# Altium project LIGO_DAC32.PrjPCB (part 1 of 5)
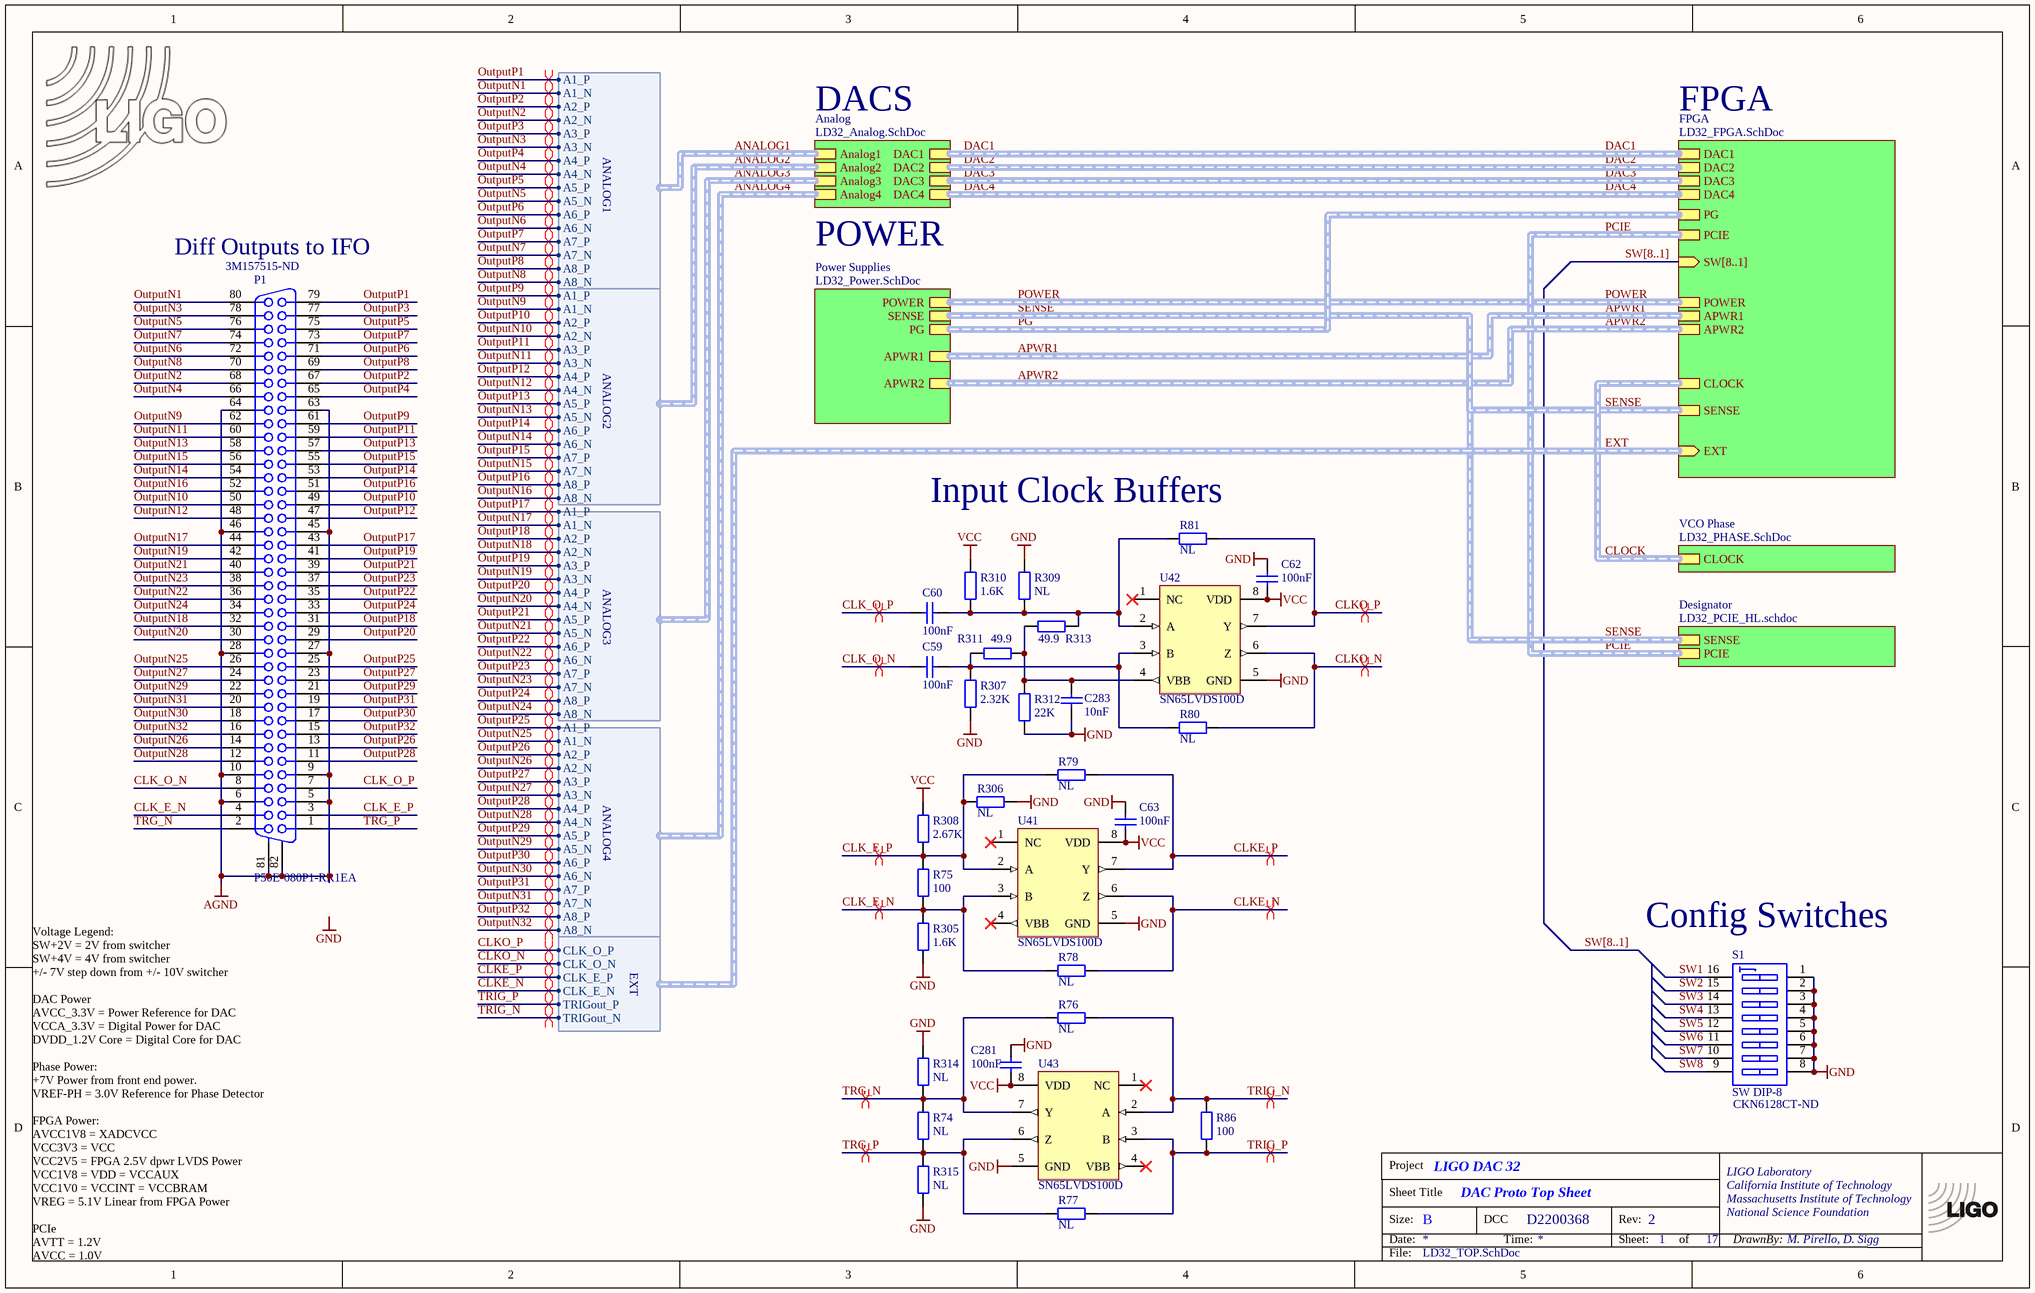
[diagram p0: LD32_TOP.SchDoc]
DCC: D2200368; DCCRevision: 2; ENG: M. Pirello, D. Sigg; Project: LIGO DAC 32; REV: 2; SHEETSIZE: B
17 sheets, 1238 parts. Net scope: hierarchical (ports join the sheet entries above them; power ports are global).
Board file: LD32.PcbDoc
Sheets:
  LD32_TOP.SchDoc
    Analog = LD32_Analog.SchDoc
      I1 = LD32_Outputs.SchDoc
         = LD32_DAC.SchDoc
           = LD32_FrontEnd.SchDoc
           = LD32_FrontEnd.SchDoc
           = LD32_FrontEnd.SchDoc
           = LD32_FrontEnd.SchDoc
      I2 = LD32_Outputs.SchDoc
         = LD32_DAC.SchDoc
           = LD32_FrontEnd.SchDoc
           = LD32_FrontEnd.SchDoc
           = LD32_FrontEnd.SchDoc
           = LD32_FrontEnd.SchDoc
      I3 = LD32_Outputs.SchDoc
         = LD32_DAC.SchDoc
           = LD32_FrontEnd.SchDoc
           = LD32_FrontEnd.SchDoc
           = LD32_FrontEnd.SchDoc
           = LD32_FrontEnd.SchDoc
      I4 = LD32_Outputs.SchDoc
         = LD32_DAC.SchDoc
           = LD32_FrontEnd.SchDoc
           = LD32_FrontEnd.SchDoc
           = LD32_FrontEnd.SchDoc
           = LD32_FrontEnd.SchDoc
    FPGA = LD32_FPGA.SchDoc
      FPGA INTERFACE = FPGA_ARTIX7.SchDoc
      ADC = LD32_XADC.SchDoc
      PRG = LD32_FLASH.SchDoc
    VCO Phase = LD32_PHASE.SchDoc
    Designator = LD32_PCIE_HL.SchDoc
      ChassisTimingInterfacePCIE = LD32_PCIE.SchDoc
    Power Supplies = LD32_Power.SchDoc
      Diff Power = LD32_Bipolar1.SchDoc
      Linear Supplies = LD32_Linear1.SchDoc
      Pos Power = LD32_Bipolar2.SchDoc
      PowerFPGA = LD32_PowerFPGA.SchDoc

## Sheet LD32_TOP.SchDoc: DAC Proto Top Sheet
size B; SheetNumber: 1; SheetTotal: 17; PageSetup: Record=PageOptions¦CenterHorizontal=True¦CenterVertical=True¦PrintScale=1.12¦XCorrection=1.00¦YCorrection=1.00¦PrintKind=0¦BorderSize=5000000¦LeftOffset=0¦BottomOffset=0¦Orientation=2¦PaperLength=1000¦PaperWidth=1000¦Scale=100¦PaperSource=7¦PrintQuality=-4¦MediaType=1¦DitherType=10¦PaperKind=Letter¦PrintScaleMode=1

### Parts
(Parts that share a designator on the sheet are numbered #1, #2 ... from top to bottom, then left to right.)
*?#1  TitleBlock  (value not drawn)  (graphical)
C59  100nF  [CC1005-0402]
C60  100nF  [CC1005-0402]
C62  100nF  [CC1005-0402]
C63  100nF  [CC1005-0402]
C281  100nF  [CC1005-0402]
C283  10nF  [CC1005-0402]
LOGO1  LIGO logo  [LIGO-LOGO-SM]  (value not drawn)  (no BOM)
P1  P50E-080P1-RR1EA  Supplier Part Number 1: 3M157515-ND  [P50E-080-SR1]
R74  NL  [CR1005-0402]
R75  100  [CR1005-0402]
R76  NL  [CR1005-0402]
R77  NL  [CR1005-0402]
R78  NL  [CR1005-0402]
R79  NL  [CR1005-0402]
R80  NL  [CR1005-0402]
R81  NL  [CR1005-0402]
R86  100  [CR1005-0402]
R305  1.6K  [CR1005-0402]
R306  NL  [CR1005-0402]
R307  2.32K  [CR1005-0402]
R308  2.67K  [CR1005-0402]
R309  NL  [CR1005-0402]
R310  1.6K  [CR1005-0402]
R311  49.9  [CR1005-0402]
R312  22K  [CR1005-0402]
R313  49.9  [CR1005-0402]
R314  NL  [CR1005-0402]
R315  NL  [CR1005-0402]
S1  SW DIP-8  Supplier Part Number 1: CKN6128CT-ND  [DIP_SW_8WAY_SMD_SIDE]
U41  SN65LVDS100D  [MSOP8]
U42  SN65LVDS100D  [MSOP8]
U43  SN65LVDS100D  [MSOP8]

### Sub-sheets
Analog = LD32_Analog.SchDoc: Analog1 (harness ANALOG1), Analog2 (harness ANALOG2), Analog3 (harness ANALOG3), Analog4 (harness ANALOG4), DAC1 (harness DAC1), DAC2 (harness DAC2), DAC3 (harness DAC3), DAC4 (harness DAC4)
Designator = LD32_PCIE_HL.schdoc: PCIE (harness PCIE), SENSE (harness SENSE)
FPGA = LD32_FPGA.SchDoc: DAC4 (harness S1_16), DAC3 (harness S17_32), DAC2 (harness S33_48), DAC1 (harness S49_64), CLOCK (harness CLOCK), PCIE (harness PCIE), POWER (harness POWER), APWR1 (harness CONFIG), APWR2 (harness CONFIG), SW[8..1] (in), PG (harness APWR2), SENSE (harness SENSE), EXT (in, harness EXT)
Power Supplies = LD32_Power.SchDoc: PG (harness APWR2), SENSE (harness SENSE), APWR1 (harness APWR2), APWR2 (harness APWR2), POWER (harness POWER)
VCO Phase = LD32_PHASE.SchDoc: CLOCK (harness CLOCK)

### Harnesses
EXT: CLK_O_N, CLK_E_P, CLK_E_N, CLK_O_P, TRIGout_P, TRIGout_N
ANALOG1: A1_P, A2_P, A2_N, A1_N, A3_P, A4_P, A4_N, A3_N, A5_P, A6_P, A6_N, A5_N, A7_P, A8_P, A8_N, A7_N
ANALOG2: A1_P, A2_P, A2_N, A1_N, A3_P, A4_P, A4_N, A3_N, A5_P, A6_P, A6_N, A5_N, A7_P, A8_P, A8_N, A7_N
ANALOG3: A1_P, A2_P, A2_N, A1_N, A3_P, A4_P, A4_N, A3_N, A5_P, A6_P, A6_N, A5_N, A7_P, A8_P, A8_N, A7_N
ANALOG4: A1_P, A2_P, A2_N, A1_N, A3_P, A4_P, A4_N, A3_N, A5_P, A6_P, A6_N, A5_N, A7_P, A8_P, A8_N, A7_N

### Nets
AGND: P1.5 P1.6 P1.9 P1.10 P1.27 P1.28 P1.45 P1.46 P1.63 P1.64 P1.81(MH1) P1.82(MH2)
GND: C62.1 C63.1 C281.1 C283.1 R305.2 R306.2 R307.2 R309.1 R312.2 R314.1 R315.2 S1.1(A1) S1.2(A2) S1.3(A3) S1.4(A4) S1.5(A5) S1.6(A6) S1.7(A7) S1.8(A8) U41.5(GND) U42.5(GND) U43.5(GND)
VCC: C62.2 C63.2 C281.2 R308.1 R310.1 U41.8(VDD) U42.8(VDD) U43.8(VDD)
CLK_E_N: P1.4 R75.2 R78.1 R305.1 U41.3(B)
CLK_E_P: P1.3 R75.1 R79.1 R306.1 R308.2 U41.2(A)
CLK_O_N: C59.1 P1.8
CLK_O_P: C60.1 P1.7
CLKE_N: R78.2 U41.6(Z) ; sheet FPGA/EXT.CLK_E_N
CLKE_P: R79.2 U41.7(Y) ; sheet FPGA/EXT.CLK_E_P
CLKO_N: R80.2 U42.6(Z) ; sheet FPGA/EXT.CLK_O_N
CLKO_P: R81.2 U42.7(Y) ; sheet FPGA/EXT.CLK_O_P
OutputN1: P1.80 ; sheet Analog/Analog1.A1_N  [project net ANALOG1.A1_N]
OutputN2: P1.68 ; sheet Analog/Analog1.A2_N  [project net ANALOG1.A2_N]
OutputN3: P1.78 ; sheet Analog/Analog1.A3_N  [project net ANALOG1.A3_N]
OutputN4: P1.66 ; sheet Analog/Analog1.A4_N  [project net ANALOG1.A4_N]
OutputN5: P1.76 ; sheet Analog/Analog1.A5_N  [project net ANALOG1.A5_N]
OutputN6: P1.72 ; sheet Analog/Analog1.A6_N  [project net ANALOG1.A6_N]
OutputN7: P1.74 ; sheet Analog/Analog1.A7_N  [project net ANALOG1.A7_N]
OutputN8: P1.70 ; sheet Analog/Analog1.A8_N  [project net ANALOG1.A8_N]
OutputN9: P1.62 ; sheet Analog/Analog2.A1_N  [project net ANALOG2.A1_N]
OutputN10: P1.50 ; sheet Analog/Analog2.A2_N  [project net ANALOG2.A2_N]
OutputN11: P1.60 ; sheet Analog/Analog2.A3_N  [project net ANALOG2.A3_N]
OutputN12: P1.48 ; sheet Analog/Analog2.A4_N  [project net ANALOG2.A4_N]
OutputN13: P1.58 ; sheet Analog/Analog2.A5_N  [project net ANALOG2.A5_N]
OutputN14: P1.54 ; sheet Analog/Analog2.A6_N  [project net ANALOG2.A6_N]
OutputN15: P1.56 ; sheet Analog/Analog2.A7_N  [project net ANALOG2.A7_N]
OutputN16: P1.52 ; sheet Analog/Analog2.A8_N  [project net ANALOG2.A8_N]
OutputN17: P1.44 ; sheet Analog/Analog3.A1_N  [project net ANALOG3.A1_N]
OutputN18: P1.32 ; sheet Analog/Analog3.A2_N  [project net ANALOG3.A2_N]
OutputN19: P1.42 ; sheet Analog/Analog3.A3_N  [project net ANALOG3.A3_N]
OutputN20: P1.30 ; sheet Analog/Analog3.A4_N  [project net ANALOG3.A4_N]
OutputN21: P1.40 ; sheet Analog/Analog3.A5_N  [project net ANALOG3.A5_N]
OutputN22: P1.36 ; sheet Analog/Analog3.A6_N  [project net ANALOG3.A6_N]
OutputN23: P1.38 ; sheet Analog/Analog3.A7_N  [project net ANALOG3.A7_N]
OutputN24: P1.34 ; sheet Analog/Analog3.A8_N  [project net ANALOG3.A8_N]
OutputN25: P1.26 ; sheet Analog/Analog4.A1_N  [project net ANALOG4.A1_N]
OutputN26: P1.14 ; sheet Analog/Analog4.A2_N  [project net ANALOG4.A2_N]
OutputN27: P1.24 ; sheet Analog/Analog4.A3_N  [project net ANALOG4.A3_N]
OutputN28: P1.12 ; sheet Analog/Analog4.A4_N  [project net ANALOG4.A4_N]
OutputN29: P1.22 ; sheet Analog/Analog4.A5_N  [project net ANALOG4.A5_N]
OutputN30: P1.18 ; sheet Analog/Analog4.A6_N  [project net ANALOG4.A6_N]
OutputN31: P1.20 ; sheet Analog/Analog4.A7_N  [project net ANALOG4.A7_N]
OutputN32: P1.16 ; sheet Analog/Analog4.A8_N  [project net ANALOG4.A8_N]
OutputP1: P1.79 ; sheet Analog/Analog1.A1_P  [project net ANALOG1.A1_P]
OutputP2: P1.67 ; sheet Analog/Analog1.A2_P  [project net ANALOG1.A2_P]
OutputP3: P1.77 ; sheet Analog/Analog1.A3_P  [project net ANALOG1.A3_P]
OutputP4: P1.65 ; sheet Analog/Analog1.A4_P  [project net ANALOG1.A4_P]
OutputP5: P1.75 ; sheet Analog/Analog1.A5_P  [project net ANALOG1.A5_P]
OutputP6: P1.71 ; sheet Analog/Analog1.A6_P  [project net ANALOG1.A6_P]
OutputP7: P1.73 ; sheet Analog/Analog1.A7_P  [project net ANALOG1.A7_P]
OutputP8: P1.69 ; sheet Analog/Analog1.A8_P  [project net ANALOG1.A8_P]
OutputP9: P1.61 ; sheet Analog/Analog2.A1_P  [project net ANALOG2.A1_P]
OutputP10: P1.49 ; sheet Analog/Analog2.A2_P  [project net ANALOG2.A2_P]
OutputP11: P1.59 ; sheet Analog/Analog2.A3_P  [project net ANALOG2.A3_P]
OutputP12: P1.47 ; sheet Analog/Analog2.A4_P  [project net ANALOG2.A4_P]
OutputP13: P1.57 ; sheet Analog/Analog2.A5_P  [project net ANALOG2.A5_P]
OutputP14: P1.53 ; sheet Analog/Analog2.A6_P  [project net ANALOG2.A6_P]
OutputP15: P1.55 ; sheet Analog/Analog2.A7_P  [project net ANALOG2.A7_P]
OutputP16: P1.51 ; sheet Analog/Analog2.A8_P  [project net ANALOG2.A8_P]
OutputP17: P1.43 ; sheet Analog/Analog3.A1_P  [project net ANALOG3.A1_P]
OutputP18: P1.31 ; sheet Analog/Analog3.A2_P  [project net ANALOG3.A2_P]
OutputP19: P1.41 ; sheet Analog/Analog3.A3_P  [project net ANALOG3.A3_P]
OutputP20: P1.29 ; sheet Analog/Analog3.A4_P  [project net ANALOG3.A4_P]
OutputP21: P1.39 ; sheet Analog/Analog3.A5_P  [project net ANALOG3.A5_P]
OutputP22: P1.35 ; sheet Analog/Analog3.A6_P  [project net ANALOG3.A6_P]
OutputP23: P1.37 ; sheet Analog/Analog3.A7_P  [project net ANALOG3.A7_P]
OutputP24: P1.33 ; sheet Analog/Analog3.A8_P  [project net ANALOG3.A8_P]
OutputP25: P1.25 ; sheet Analog/Analog4.A1_P  [project net ANALOG4.A1_P]
OutputP26: P1.13 ; sheet Analog/Analog4.A2_P  [project net ANALOG4.A2_P]
OutputP27: P1.23 ; sheet Analog/Analog4.A3_P  [project net ANALOG4.A3_P]
OutputP28: P1.11 ; sheet Analog/Analog4.A4_P  [project net ANALOG4.A4_P]
OutputP29: P1.21 ; sheet Analog/Analog4.A5_P  [project net ANALOG4.A5_P]
OutputP30: P1.17 ; sheet Analog/Analog4.A6_P  [project net ANALOG4.A6_P]
OutputP31: P1.19 ; sheet Analog/Analog4.A7_P  [project net ANALOG4.A7_P]
OutputP32: P1.15 ; sheet Analog/Analog4.A8_P  [project net ANALOG4.A8_P]
SW1: S1.16(B1)
SW2: S1.15(B2)
SW3: S1.14(B3)
SW4: S1.13(B4)
SW5: S1.12(B5)
SW6: S1.11(B6)
SW7: S1.10(B7)
SW8: S1.9(B8)
TRG_N: P1.2 R74.1 R76.2 R314.2 U43.7(Y)
TRG_P: P1.1 R74.2 R77.2 R315.1 U43.6(Z)
TRIG_N: R76.1 R86.1 U43.2(A) ; sheet FPGA/EXT.TRIGout_N  [project net EXT.TRIGout_N]
TRIG_P: R77.1 R86.2 U43.3(B) ; sheet FPGA/EXT.TRIGout_P  [project net EXT.TRIGout_P]
NetC59_2: C59.2 R80.1 R307.1 R311.2 U42.3(B)
NetC60_2: C60.2 R81.1 R309.2 R310.2 R313.1 U42.2(A)
NetC283_2: C283.2 R311.1 R312.1 R313.2 U42.4(VBB)

Not connected (* = marked no-connect by the designer): U41 1(NC)* 4(VBB)*; U42 1(NC)*; U43 1(NC)* 4(VBB)*

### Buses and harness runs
bus SW[8..1] = sheet FPGA/SW[8..1]
harness ANALOG1 = sheet Analog/Analog1
harness ANALOG2 = sheet Analog/Analog2
harness ANALOG3 = sheet Analog/Analog3
harness ANALOG4 = sheet Analog/Analog4
harness APWR1 = sheet FPGA/APWR1 = sheet Power Supplies/APWR1
harness APWR2 = sheet FPGA/APWR2 = sheet Power Supplies/APWR2
harness CLOCK = sheet FPGA/CLOCK = sheet VCO Phase/CLOCK
harness DAC1 = sheet Analog/DAC1 = sheet FPGA/DAC1
harness DAC2 = sheet Analog/DAC2 = sheet FPGA/DAC2
harness DAC3 = sheet Analog/DAC3 = sheet FPGA/DAC3
harness DAC4 = sheet Analog/DAC4 = sheet FPGA/DAC4
harness EXT = sheet FPGA/EXT
harness PCIE = sheet Designator/PCIE = sheet FPGA/PCIE
harness PG = sheet FPGA/PG = sheet Power Supplies/PG
harness POWER = sheet FPGA/POWER = sheet Power Supplies/POWER
harness SENSE = sheet Designator/SENSE = sheet FPGA/SENSE = sheet Power Supplies/SENSE

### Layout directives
differential pair: ANALOG1.A1_N, ANALOG1.A1_P, ANALOG1.A2_N, ANALOG1.A2_P, ANALOG1.A3_N, ANALOG1.A3_P, ANALOG1.A4_N, ANALOG1.A4_P, ANALOG1.A5_N, ANALOG1.A5_P, ANALOG1.A6_N, ANALOG1.A6_P, ANALOG1.A7_N, ANALOG1.A7_P, ANALOG1.A8_N, ANALOG1.A8_P, ANALOG2.A1_N, ANALOG2.A1_P, ANALOG2.A2_N, ANALOG2.A2_P, ANALOG2.A3_N, ANALOG2.A3_P, ANALOG2.A4_N, ANALOG2.A4_P, ANALOG2.A5_N, ANALOG2.A5_P, ANALOG2.A6_N, ANALOG2.A6_P, ANALOG2.A7_N, ANALOG2.A7_P, ANALOG2.A8_N, ANALOG2.A8_P, ANALOG3.A1_N, ANALOG3.A1_P, ANALOG3.A2_N, ANALOG3.A2_P, ANALOG3.A3_N, ANALOG3.A3_P, ANALOG3.A4_N, ANALOG3.A4_P, ANALOG3.A5_N, ANALOG3.A5_P, ANALOG3.A6_N, ANALOG3.A6_P, ANALOG3.A7_N, ANALOG3.A7_P, ANALOG3.A8_N, ANALOG3.A8_P, ANALOG4.A1_N, ANALOG4.A1_P, ANALOG4.A2_N, ANALOG4.A2_P, ANALOG4.A3_N, ANALOG4.A3_P, ANALOG4.A4_N, ANALOG4.A4_P, ANALOG4.A5_N, ANALOG4.A5_P, ANALOG4.A6_N, ANALOG4.A6_P, ANALOG4.A7_N, ANALOG4.A7_P, ANALOG4.A8_N, ANALOG4.A8_P, CLK_E_N, CLK_E_P, CLK_O_N, CLK_O_P, CLKE_N, CLKE_P, CLKO_N, CLKO_P, EXT.TRIGout_N, EXT.TRIGout_P, TRG_N, TRG_P

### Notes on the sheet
- DACS
- FPGA
- (near P1) Diff Outputs to IFO
- POWER
- (near R81) Input Clock Buffers
- (near S1) Config Switches
- Voltage Legend:
  SW+2V = 2V from switcher
  SW+4V = 4V from switcher
  +/- 7V step down from +/- 10V switcher
  DAC Power
  AVCC_3.3V = Power Reference for DAC
  VCCA_3.3V = Digital Power for DAC
  DVDD_1.2V Core = Digital Core for DAC
  Phase Power:
  +7V Power from front end power.
  VREF-PH = 3.0V Reference for Phase Detector
  FPGA Power:
  AVCC1V8 = XADCVCC
  VCC3V3 = VCC
  VCC2V5 = FPGA 2.5V dpwr LVDS Power
  VCC1V8 = VDD = VCCAUX
  VCC1V0 = VCCINT = VCCBRAM
  VREG = 5.1V Linear from FPGA Power
  PCIe
  AVTT = 1.2V
  AVCC = 1.0V
- Labels drawn without touching a wire or pin: GND

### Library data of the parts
C59 C60 C62 C63 C281 = ChipCap: C0402 0.1uF; Part Number: CL05B104KA5NNNC
C283 = ChipCap: C0402 0.01uF; Part Number: CC0402JRX7R9BB103
LOGO1 = LIGO_logo: NL
P1 = PE50E-080 Connector: 3M Pak 50 plug connector; Part Number: P50E-080P1-SR1-EA
R74 R76-R81 R306 R309 R314 R315 = ChipRes1
R75 R86 = ChipRes1: R0402 100; Part Number: RR0510P-101-D
R305 R310 = ChipRes1: R0402 1.6k; Part Number: ERA-2AEB162X
R307 = ChipRes1: R0402 2.32k; Part Number: ERA-2AEB2321X
R308 = ChipRes1: R0402  2.67k; Part Number: ERA-2AEB2671X
R311 R313 = ChipRes1: R0402 49.9; Part Number: ERA-2AEB49R9X
R312 = ChipRes1: R0402 22k; Part Number: ERA-2AED223X
S1 = SW DIP-8: DIP Switch, 8 Position, SPST
U41-U43 = SN65LVDS100: DIFF TRANSLATOR; Part Number: SN65LVDS100DGKR

## Sheet LD32_Analog.SchDoc: DAC Top
size B; SheetNumber: 12; SheetTotal: 17; SPICEModelCacheMGJMTSKS: <root> / <DocumentId>MGJMTSKS</DocumentId> / <CacheFrame Number="0"> / <Model Name="op284f" Kind="CKT"> / <Text>* OP284F SPICE Macro-model              11/95 / Rev. B / *                                       ARG / ADSC / * / * Revision History: / * / *     Rev. B / * Changed the short-circuit output current limit from +/- 7.5mA / * to +/- 6.5mA to reflect final data sheet limits. / * / * Changed Vos spec to conform to final data sheet value of / * 125uV, up from 50uV. / * / * / * This version of the OP284 model simulates the worst-case / * parameters of the 'F' grade.  The worst-case parameters / * used correspond to those in the data sheet. / * / * Copyright 1993 by Analog Devices / * / * Refer to "README.DOC" file for License Statement. Use of this model / * indicates your acceptance of the terms and provisions in the License / * Statement. / * / * Node assignments / *                non-inverting input / *                ¦   inverting input / *                ¦   ¦   positive supply / *                ¦   ¦   ¦   negative supply / *                ¦   ¦   ¦   ¦   output / *                ¦   ¦   ¦   ¦   ¦ / .SUBCKT OP284F   1   2   99  50  45 / * / * INPUT STAGE / * / Q1   5    2    3    QIN 1 / Q2   6    11   3    QIN 1 / Q3   7    2    4    QIP 1 / Q4   8    11   4    QIP 1 / DC1  2    11   DC / DC2  11   2    DC / Q5   4    9    99   QIP 1 / Q6   9    9    99   QIP 1 / Q7   3    10   50   QIN 1 / Q8   10   10   50   QIN 1 / R1   99   5    4E3 / R2   99   6    4E3 / R3   7    50   4E3 / R4   8    50   4E3 / IREF 9    10   50.5E-6 / EOS  1    11   POLY(2) (22,98) (14,98) -125E-6 501.2E-3 1 / IOS  2    1    25E-9 / CIN  1    2    2E-12 / GN1  98   1    17 98 1E-3 / GN2  98   2    23 98 1E-3 / * / * VOLTAGE NOISE SOURCE WITH FLICKER NOISE / * / VN1  13   98   DC 2 / VN2  98   15   DC 2 / DN1  13   14   DEN / DN2  14   15   DEN / * / * CURRENT NOISE SOURCE WITH FLICKER NOISE / * / VN3  16   98   DC 2 / VN4  98   18   DC 2 / DN3  16   17   DIN / DN4  17   18   DIN / * / * 2ND CURRENT NOISE SOURCE WITH FLICKER NOISE / * / VN5  19   98   DC 2 / VN6  98   24   DC 2 / DN5  19   23   DIN / DN6  23   24   DIN / * / * GAIN STAGE / * / EREF 98   0    POLY(2) (99,0) (50,0) 0 0.5 0.5 / G1   98   20   POLY(2) (6,5) (8,7) 0 0.5E-3 0.5E-3 / R9   20   98   1E3 / * / * COMMON MODE STAGE WITH ZERO AT 5KHZ / * / ECM  98   21   POLY(2) (1,98) (2,98) 0 0.5 0.5 / R10  21   22   1 / R11  22   98   100E-6 / C4   21   22   31.756E-6 / * / * NEGATIVE ZERO AT 20MHZ / * / E1   27   98   20 98 1 / R17  27   28   1 / R18  28   98   1E-6 / C8   25   26   7.958E-9 / ENZ  25   98   27 28 1 / VNZ  26   98   DC 0 / FNZ  27   28   VNZ -1 / * / * POLE AT 40MHZ / * / G4   98   29   28 98 1E6 / R19  29   98   1 / C9   29   98   3.979E-9 / * / * POLE AT 40MHZ / * / G5   98   30   29 98 1 / R20  30   98   1 / C10  30   98   3.979E-9 / * / * OUTUT STAGE / * / ISY  99   50   0.526E-3 / GIN  50   31   POLY(1) (30,98) 0.862574E-6 511.855E-6 / RIN  31   50   2.75E6 / VB   99   32   0.7 / Q11  32   31   33   QON 1 / R21  33   34   4.5E3 / I1   34   50   50E-6 / R22  99   35   6E3 / Q12  36   36   35   QOP 1 / I2   36   50   50E-6 / R23  99   37   2.6E3 / R24  34   38   5E3 / Q13  39   36   37   QOP 1 / Q14  39   38   40   QON 1.5 / R25  40   50   40 / Q15  39   39   41   QON 1 / R26  41   42   1E3 / R27  99   43   220 / Q16  44   44   43   QOP 1.5 / Q17  44   39   42   QON 1 / R28  42   50   2E3 / VSCP 99   97   DC 0 / FSCP 46   99   VSCP 1 / RSCP 46   99   125 / Q20  44   46   99   QOP 1 / Q18  45   44   97   QOP 4.5 / Q19  45   34   51   QON 4.5 / VSCN 51   50   DC 0 / FSCN 50   47   VSCN 1 / RSCN 47   50   122 / Q21  34   47   50   QON 1 / CC2  31   45   20E-12 / CF1  31   34   15E-12 / CF2  31   42   15E-12 / CO1  34   45   15E-12 / CO2  42   45   5E-12 / D3   45   99   DX / D4   50   45   DX / .MODEL DC D(IS=130E-21) / .MODEL DX D() / .MODEL DEN D(RS=100 KF=12E-15 AF=1) / .MODEL DIN D(RS=5.358 KF=56E-15 AF=1) / .MODEL QIN NPN(BF=250 VA=200 IS=0.5E-16) / .MODEL QIP PNP(BF=60 VA=100 IS=0.5E-16) / .MODEL QON NPN(BF=200 VA=200 IS=0.5E-16 RC=140) / .MODEL QOP PNP(BF=200 VA=200 IS=0.5E-16 RC=210) / .ENDS</Text> / </Model> / </CacheFrame> / </root>
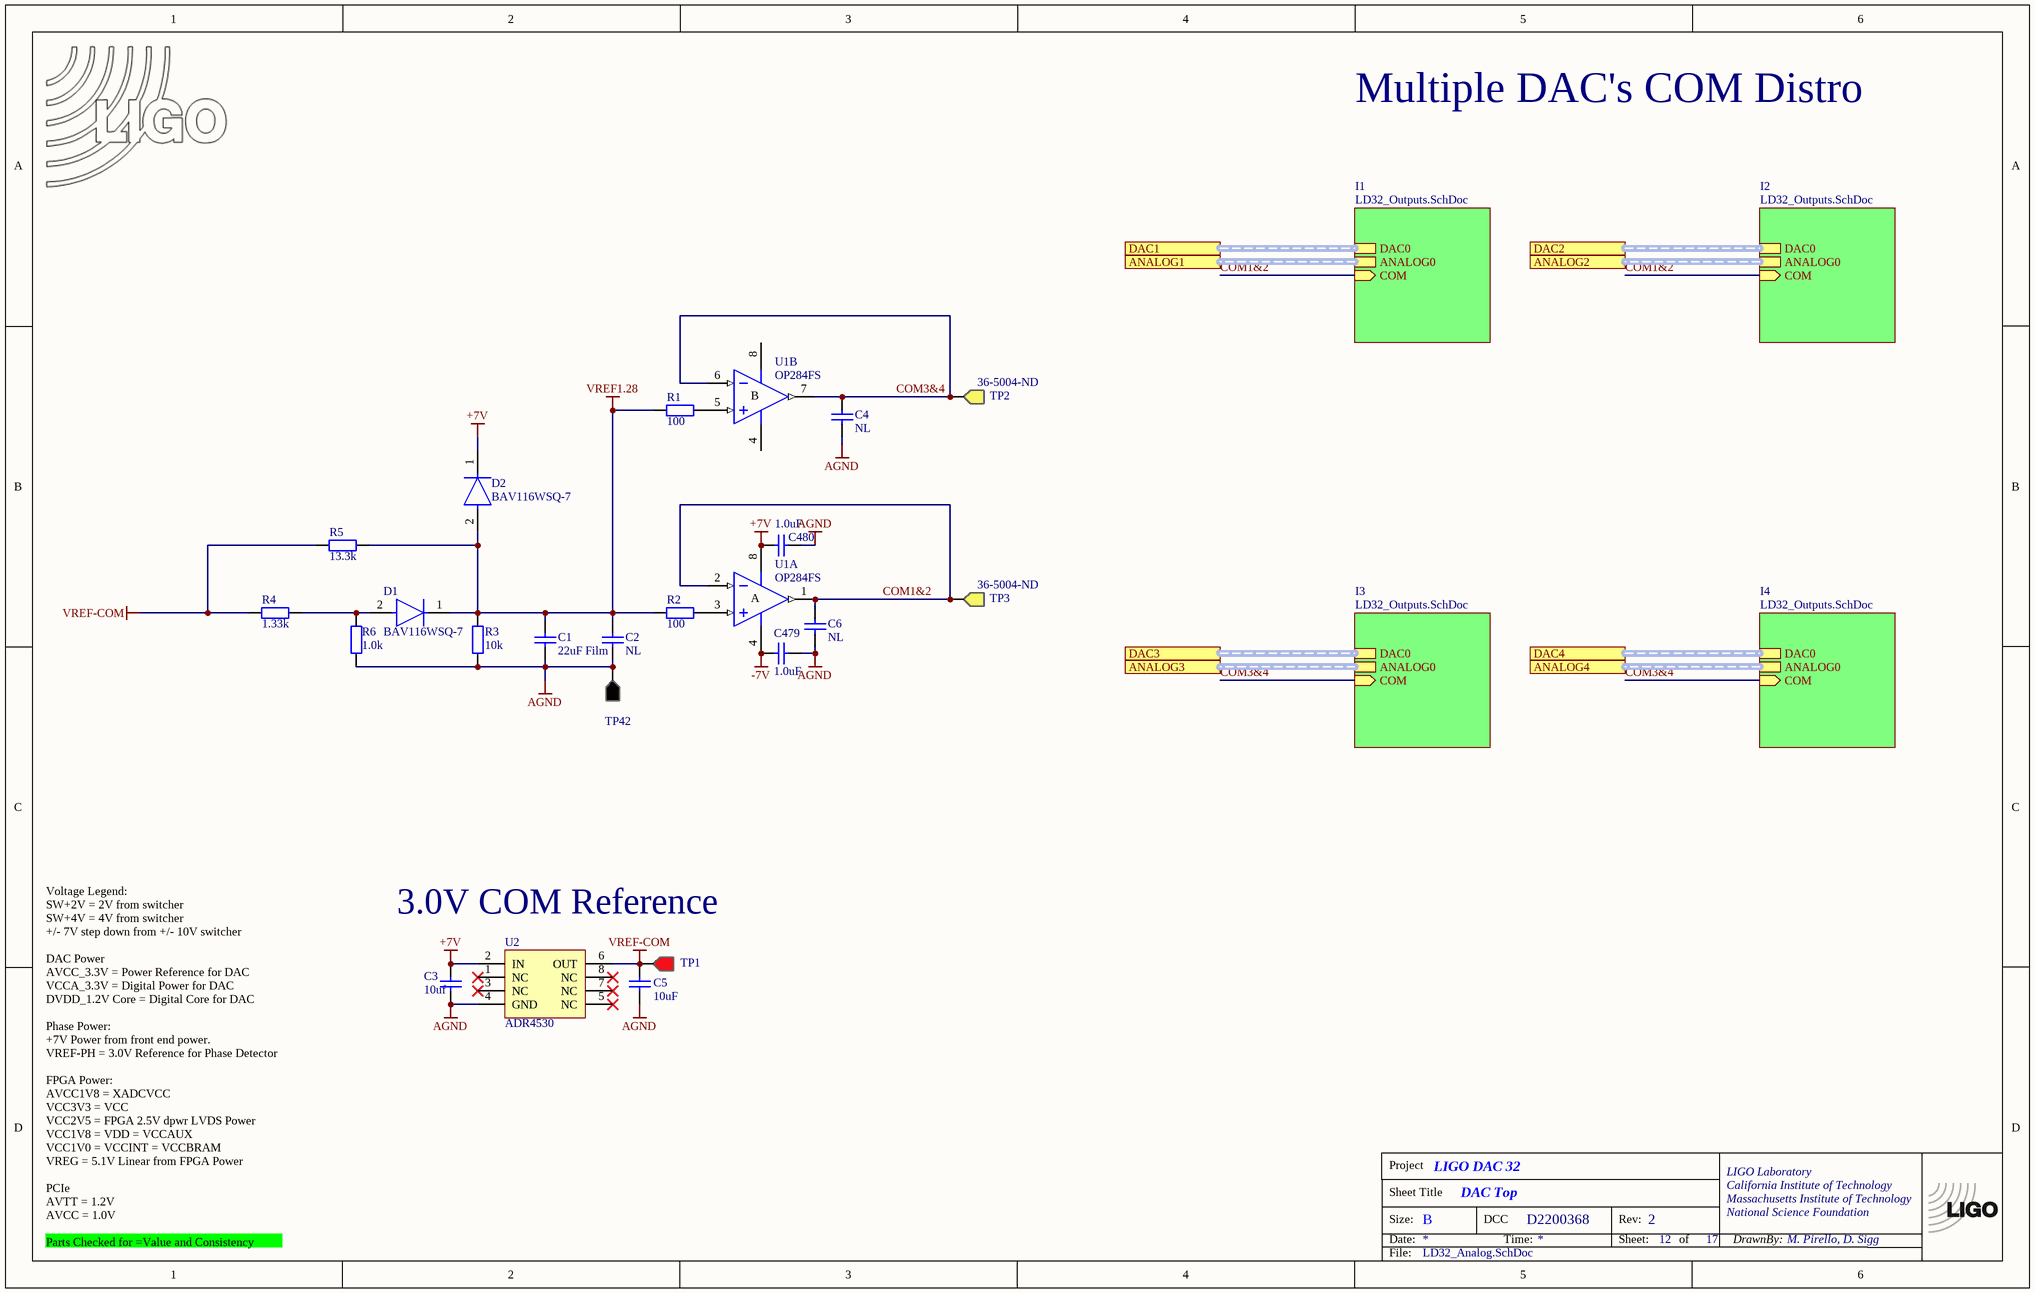
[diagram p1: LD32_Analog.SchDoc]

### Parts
(Parts that share a designator on the sheet are numbered #1, #2 ... from top to bottom, then left to right.)
*?#2  TitleBlock  (value not drawn)  (graphical)
C1  value 22uF Film  [CC5650-2220]  (hidden comment: 22uF)
C2  NL  [CC1005-0402]
C3  10uF  [CC3225-1210]
C4  NL  [CC1608-0603]
C5  10uF  [CC3225-1210]
C6  NL  [CC1608-0603]
C479  1.0uF  [CC1608-0603]
C480  1.0uF  [CC1608-0603]
D1  BAV116WSQ-7  [FP-SOD323-MFG]
D2  BAV116WSQ-7  [FP-SOD323-MFG]
LOGO?#1  LIGO logo  [LIGO_LOGO]  (value not drawn)  (graphical)
R1  100  [CR1005-0402]
R2  100  [CR1005-0402]
R3  10k  [CR1005-0402]
R4  1.33k  [CR1005-0402]
R5  13.3k  [CR1005-0402]
R6  1.0k  [CR1005-0402]
TP1  Testpoint  [TP1-RED]  (value not drawn)
TP2  Supplier Part Number 1: 36-5004-ND  [TP1-YLW]  (hidden comment: Testpoint)
TP3  Supplier Part Number 1: 36-5004-ND  [TP1-YLW]  (hidden comment: Testpoint)
TP42  Testpoint  [TP1-BLK]  (value not drawn)
U1  OP284FS  [SO-8_N]  (parts A,B of 2)
U2  ADR4530  [SO-G8]

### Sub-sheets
I1 = LD32_Outputs.SchDoc: ANALOG0 (harness DAC), DAC0 (harness DAC), COM (in)
I2 = LD32_Outputs.SchDoc: ANALOG0 (harness ANALOG2), DAC0 (harness DAC), COM (in)
I3 = LD32_Outputs.SchDoc: ANALOG0 (harness ANALOG3), DAC0 (harness DAC), COM (in)
I4 = LD32_Outputs.SchDoc: ANALOG0 (harness ANALOG4), DAC0 (harness DAC), COM (in)

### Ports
ANALOG1 (harness DAC), ANALOG2 (harness ANALOG), ANALOG3 (harness ANALOG), ANALOG4 (harness ANALOG), DAC1 (harness ANALOG), DAC2 (harness ANALOG), DAC3 (harness ANALOG), DAC4 (harness ANALOG)

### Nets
+7V: C3.1 C480.2 D2.1(C) U1.8(V+) U2.2(IN)
-7V: C479.2 U1.4(V-)
AGND: C1.1 C2.2 C3.2 C4.2 C5.1 C6.2 C479.1 C480.1 R3.1 R6.1 TP42.1 U2.4(GND)
VREF1.28: C1.2 C2.1 D1.1(C) D2.2(A) R1.2 R2.2 R3.2 R5.2
VREF-COM: C5.2 R4.1 R5.1 TP1.1 U2.6(OUT)
COM1&2: C6.1 TP3.1 U1.1(OUT) U1.2(IN-) ; sheet I1/COM, sheet I2/COM
COM3&4: C4.1 TP2.1 U1.6(IN-) U1.7(OUT) ; sheet I3/COM, sheet I4/COM
NetD1_2: D1.2(A) R4.2 R6.2
NetR1_1: R1.1 U1.5(IN+)
NetR2_1: R2.1 U1.3(IN+)

Not connected (* = marked no-connect by the designer): U2 1(NC)* 3(NC)* 5(NC)* 7(NC)* 8(NC)*

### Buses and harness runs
harness port ANALOG1 = sheet I1/ANALOG0
harness port ANALOG2 = sheet I2/ANALOG0
harness port ANALOG3 = sheet I3/ANALOG0
harness port ANALOG4 = sheet I4/ANALOG0
harness port DAC1 = sheet I1/DAC0
harness port DAC2 = sheet I2/DAC0
harness port DAC3 = sheet I3/DAC0
harness port DAC4 = sheet I4/DAC0

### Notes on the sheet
- Multiple DAC's COM Distro
- 3.0V COM Reference
- Parts Checked for =Value and Consistency
- Voltage Legend:
  SW+2V = 2V from switcher
  SW+4V = 4V from switcher
  +/- 7V step down from +/- 10V switcher
  DAC Power
  AVCC_3.3V = Power Reference for DAC
  VCCA_3.3V = Digital Power for DAC
  DVDD_1.2V Core = Digital Core for DAC
  Phase Power:
  +7V Power from front end power.
  VREF-PH = 3.0V Reference for Phase Detector
  FPGA Power:
  AVCC1V8 = XADCVCC
  VCC3V3 = VCC
  VCC2V5 = FPGA 2.5V dpwr LVDS Power
  VCC1V8 = VDD = VCCAUX
  VCC1V0 = VCCINT = VCCBRAM
  VREG = 5.1V Linear from FPGA Power
  PCIe
  AVTT = 1.2V
  AVCC = 1.0V

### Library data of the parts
C1 = ChipCap: C2220 22uF; Part Number: 16MU226MD35750
C2 C4 C6 = ChipCap
C3 C5 = ChipCap: C1210 10uF; Part Number: CL32B106KBJNNNE
C479 C480 = ChipCap: C0603 1.0uF; Part Number: CL10B105KA8NNNC
D1 D2 = CMP-12791-000031-1: DIODE GEN PURP 85V 215MA SOD323; Value: 1.5pF
LOGO?#1 = LIGO_logo
R1 R2 = ChipRes1: R0402 100; Part Number: RR0510P-101-D
R3 = ChipRes1: R0402 10k; Part Number: ERA-2AEB103X
R4 = ChipRes1: R0402 1.33k; Part Number: ERA-2AEB1331X
R5 = ChipRes1: R0402 13.3k; Part Number: ERA-2AEB1332X
R6 = ChipRes1: R0402 1.0k; Part Number: ERA-2AEB102X
TP1 = TP_POSITIVE: Testpoint, red; Part Number: Keystone / 5000
TP2 TP3 = TP_SIGNAL: Testpoint, yellow; Part Number: Keystone / 5004
TP42 = TP_GND: Testpoint, black; Part Number: Keystone / 5001
U1 = OP284FS: Precision Rail-to-Rail Input and Output Operational Amplifier; Part Number: OP284FSZ-REEL7
U2 = ADR292ER: Low-Noise Micropower Precision Voltage Reference; Part Number: ADR4530ARZ-R7

## Sheet LD32_Outputs.SchDoc: DAC Overview
size B; SheetNumber: 13; SheetTotal: 17
Used 4 times, as channels Analog/I1, Analog/I2, Analog/I3, Analog/I4. Parts and nets are listed once, with the designators drawn on the sheet.
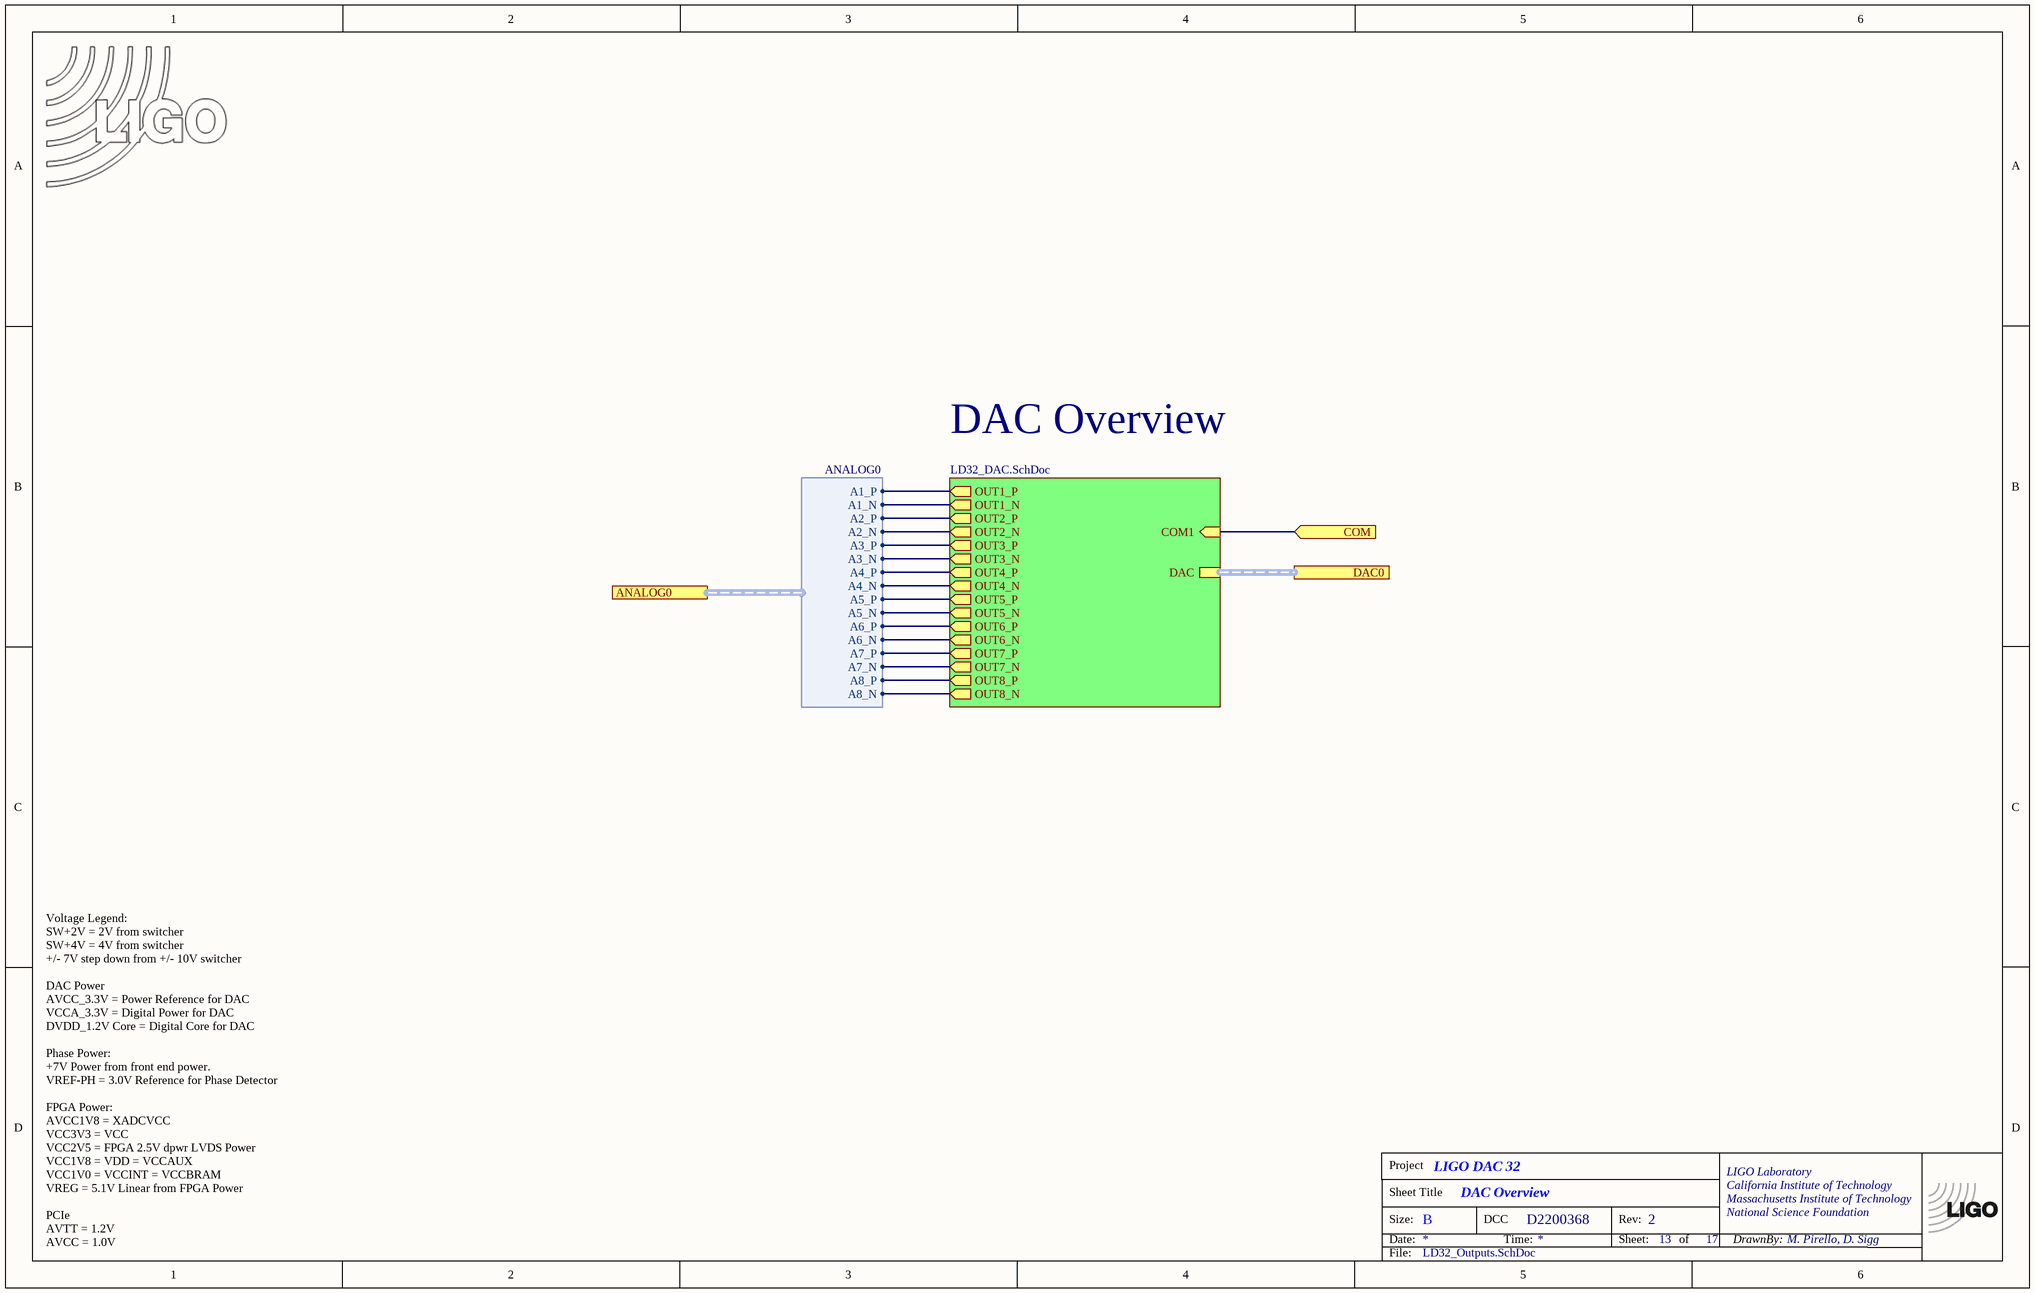
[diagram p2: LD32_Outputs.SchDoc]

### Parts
*?  TitleBlock  (value not drawn)  (graphical)
LOGO?  LIGO logo  [LIGO_LOGO]  (value not drawn)  (graphical)

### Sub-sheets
? = LD32_DAC.SchDoc: OUT1_P (out), OUT1_N (out), OUT2_P (out), OUT2_N (out), OUT3_P (out), OUT3_N (out), OUT4_P (out), OUT4_N (out), DAC (harness DAC), OUT5_P (out), OUT5_N (out), OUT6_P (out), OUT6_N (out), OUT7_P (out), OUT7_N (out), OUT8_P (out), OUT8_N (out), COM1 (in)

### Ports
ANALOG0 (harness ANALOG0), COM (in), DAC0 (harness DAC)

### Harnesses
ANALOG0: A1_P, A2_P, A2_N, A1_N, A3_P, A4_P, A4_N, A3_N, A5_P, A6_P, A6_N, A5_N, A7_P, A8_P, A8_N, A7_N

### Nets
COM: port COM, sheet /COM1
(unnamed): sheet /OUT1_P, port ANALOG0.A1_P
(unnamed): sheet /OUT1_N, port ANALOG0.A1_N  [a separate net that carries the same name]
(unnamed): sheet /OUT2_P, port ANALOG0.A2_P  [a separate net that carries the same name]
(unnamed): sheet /OUT2_N, port ANALOG0.A2_N  [a separate net that carries the same name]
(unnamed): sheet /OUT3_P, port ANALOG0.A3_P  [a separate net that carries the same name]
(unnamed): sheet /OUT3_N, port ANALOG0.A3_N  [a separate net that carries the same name]
(unnamed): sheet /OUT4_P, port ANALOG0.A4_P  [a separate net that carries the same name]
(unnamed): sheet /OUT4_N, port ANALOG0.A4_N  [a separate net that carries the same name]
(unnamed): sheet /OUT5_P, port ANALOG0.A5_P  [a separate net that carries the same name]
(unnamed): sheet /OUT5_N, port ANALOG0.A5_N  [a separate net that carries the same name]
(unnamed): sheet /OUT6_P, port ANALOG0.A6_P  [a separate net that carries the same name]
(unnamed): sheet /OUT6_N, port ANALOG0.A6_N  [a separate net that carries the same name]
(unnamed): sheet /OUT7_P, port ANALOG0.A7_P  [a separate net that carries the same name]
(unnamed): sheet /OUT7_N, port ANALOG0.A7_N  [a separate net that carries the same name]
(unnamed): sheet /OUT8_P, port ANALOG0.A8_P  [a separate net that carries the same name]
(unnamed): sheet /OUT8_N, port ANALOG0.A8_N  [a separate net that carries the same name]

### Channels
Analog/I1: designators end in A#1; ports COM=COM1&2
Analog/I2: designators end in B#2; ports COM=COM1&2
Analog/I3: designators end in C#2; ports COM=COM3&4
Analog/I4: designators end in D#2; ports COM=COM3&4

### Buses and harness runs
harness port DAC0 = sheet /DAC

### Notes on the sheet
- DAC Overview
- Voltage Legend:
  SW+2V = 2V from switcher
  SW+4V = 4V from switcher
  +/- 7V step down from +/- 10V switcher
  DAC Power
  AVCC_3.3V = Power Reference for DAC
  VCCA_3.3V = Digital Power for DAC
  DVDD_1.2V Core = Digital Core for DAC
  Phase Power:
  +7V Power from front end power.
  VREF-PH = 3.0V Reference for Phase Detector
  FPGA Power:
  AVCC1V8 = XADCVCC
  VCC3V3 = VCC
  VCC2V5 = FPGA 2.5V dpwr LVDS Power
  VCC1V8 = VDD = VCCAUX
  VCC1V0 = VCCINT = VCCBRAM
  VREG = 5.1V Linear from FPGA Power
  PCIe
  AVTT = 1.2V
  AVCC = 1.0V

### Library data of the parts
LOGO? = LIGO_logo

## Sheet LD32_DAC.SchDoc: DAC
size B; SheetNumber: 14; SheetTotal: 17
Used 4 times, as channels Analog/I1/, Analog/I2/, Analog/I3/, Analog/I4/. Parts and nets are listed once, with the designators drawn on the sheet.
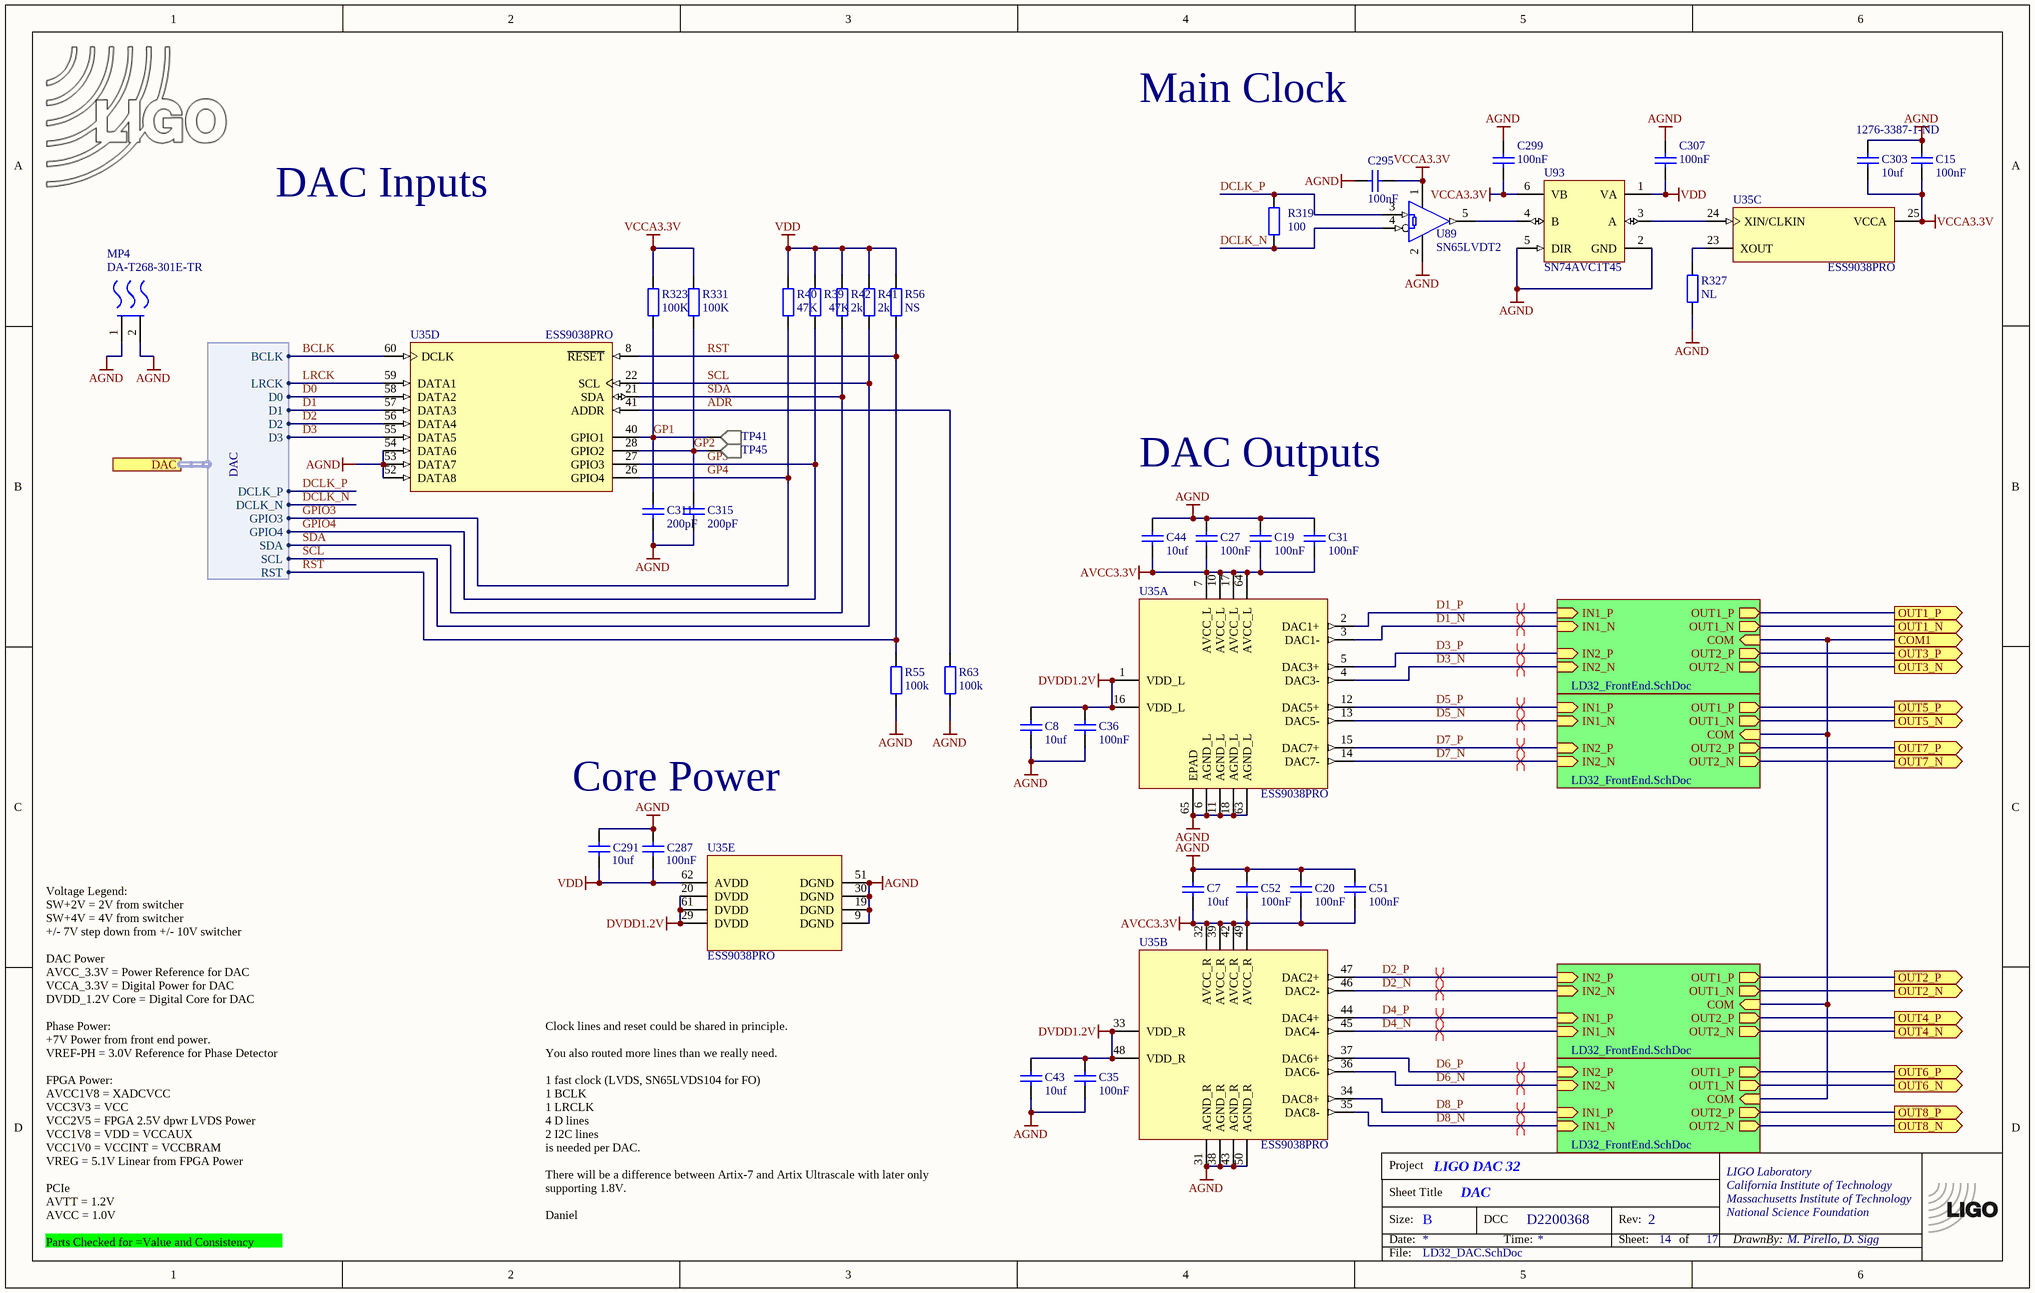
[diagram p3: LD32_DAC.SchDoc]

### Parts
*?  TitleBlock  (value not drawn)  (graphical)
C7  10uf  [CC3225-1210]
C8  10uf  [CC3225-1210]
C15  100nF  [CC0603-0201]
C19  100nF  [CC0603-0201]
C20  100nF  [CC0603-0201]
C27  100nF  [CC0603-0201]
C31  100nF  [CC0603-0201]
C35  100nF  [CC0603-0201]
C36  100nF  [CC0603-0201]
C43  10uf  [CC3225-1210]
C44  10uf  [CC3225-1210]
C51  100nF  [CC0603-0201]
C52  100nF  [CC0603-0201]
C287  100nF  [CC0603-0201]
C291  10uF  [CC3225-1210]
C295  100nF  [CC0603-0201]
C299  100nF  [CC0603-0201]
C303  Supplier Part Number 1: 1276-3387-1-ND  [CC3225-1210]  (hidden comment: 10uF)
C307  100nF  [CC0603-0201]
C311  200pF  [CC1005-0402]
C315  200pF  [CC1005-0402]
LOGO?  LIGO logo  [LIGO_LOGO]  (value not drawn)  (graphical)
MP4  DA-T268-301E-TR  [FP-DA-T268-301E-TR-MFG]
R39  47K  [CR0603-0201]
R40  47K  [CR0603-0201]
R41  2k  [CR0603-0201]
R42  2k  [CR0603-0201]
R55  100k  [CR0603-0201]
R56  NS  [CR0603-0201]
R63  100k  [CR0603-0201]
R319  100  [CR1005-0402]
R323  100K  [CR1005-0402]
R327  NL  [CR1005-0402]
R331  100K  [CR1005-0402]
TP41  Testpoint  [TP2]  (value not drawn)
TP45  Testpoint  [TP2]  (value not drawn)
U35  ESS9038PRO  [CP-64_3_MXM]  (parts A,B,C,D,E of 5)
U89  SN65LVDT2  [SO-G5/E2.4]
U93  SN74AVC1T45  [SO-G6/E2.4]

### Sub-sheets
? = LD32_FrontEnd.SchDoc: IN1_P (in), IN1_N (in), OUT1_P (out), OUT1_N (out), COM (in), IN2_P (in), IN2_N (in), OUT2_P (out), OUT2_N (out)
? = LD32_FrontEnd.SchDoc: IN1_P (in), IN1_N (in), OUT1_P (out), OUT1_N (out), COM (in), IN2_P (in), IN2_N (in), OUT2_P (out), OUT2_N (out)
? = LD32_FrontEnd.SchDoc: IN1_P (in), IN1_N (in), OUT1_P (out), OUT1_N (out), COM (in), IN2_P (in), IN2_N (in), OUT2_P (out), OUT2_N (out)
? = LD32_FrontEnd.SchDoc: IN1_P (in), IN1_N (in), OUT1_P (out), OUT1_N (out), COM (in), IN2_P (in), IN2_N (in), OUT2_P (out), OUT2_N (out)

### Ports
COM1 (out), DAC (harness DAC), OUT1_N (out), OUT1_P (out), OUT2_N (out), OUT2_P (out), OUT3_N (out), OUT3_P (out), OUT4_N (out), OUT4_P (out), OUT5_N (out), OUT5_P (out), OUT6_N (out), OUT6_P (out), OUT7_N (out), OUT7_P (out), OUT8_N (out), OUT8_P (out)

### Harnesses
DAC: BCLK, LRCK, D0, D1, D2, D3, SCL, SDA, RST, GPIO4, GPIO3, DCLK_N, DCLK_P

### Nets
AGND: C7.1 C8.2 C15.1 C19.1 C20.1 C27.1 C31.1 C35.2 C36.2 C43.2 C44.1 C51.1 C52.1 C287.2 C291.1 C295.2 C299.1 C303.1 C307.1 C311.2 C315.2 MP4.1(MNT_1) MP4.2(MNT_2) R55.1 R63.1 R327.1 U35.6(AGND_L) U35.9(DGND) U35.11(AGND_L) U35.18(AGND_L) U35.19(DGND) U35.30(DGND) U35.31(AGND_R) U35.38(AGND_R) U35.43(AGND_R) U35.50(AGND_R) U35.51(DGND) U35.52(DATA8) U35.53(DATA7) U35.54(DATA6) U35.63(AGND_L) U35.65(EPAD) U89.2(GND) U93.2(GND) U93.5(DIR)
AVCC3.3V: C7.2 C19.2 C20.2 C27.2 C31.2 C44.2 C51.2 C52.2 U35.7(AVCC_L) U35.10(AVCC_L) U35.17(AVCC_L) U35.32(AVCC_R) U35.39(AVCC_R) U35.42(AVCC_R) U35.49(AVCC_R) U35.64(AVCC_L)
DVDD1.2V: C8.1 C35.1 C36.1 C43.1 U35.1(VDD_L) U35.16(VDD_L) U35.20(DVDD) U35.29(DVDD) U35.33(VDD_R) U35.48(VDD_R) U35.61(DVDD)
VCCA3.3V: C15.2 C295.1 C299.2 C303.2 R323.2 R331.2 U35.25(VCCA) U89.1(VCC) U93.6(VB)
VDD: C287.1 C291.2 C307.2 R39.2 R40.2 R41.2 R42.2 R56.2 U35.62(AVDD) U93.1(VA)
ADR: R63.2 U35.41(ADDR)
BCLK: U35.60(DCLK) ; port DAC.BCLK
COM1: port COM1, sheet /COM, sheet /COM, sheet /COM, sheet /COM
D0: U35.58(DATA2) ; port DAC.D0
D1: U35.57(DATA3) ; port DAC.D1
D1_N: U35.3(DAC1-) ; sheet /IN1_N
D1_P: U35.2(DAC1+) ; sheet /IN1_P
D2: U35.56(DATA4) ; port DAC.D2
D2_N: U35.46(DAC2-) ; sheet /IN2_N
D2_P: U35.47(DAC2+) ; sheet /IN2_P
D3: U35.55(DATA5) ; port DAC.D3
D3_N: U35.4(DAC3-) ; sheet /IN2_N
D3_P: U35.5(DAC3+) ; sheet /IN2_P
D4_N: U35.45(DAC4-) ; sheet /IN1_N
D4_P: U35.44(DAC4+) ; sheet /IN1_P
D5_N: U35.13(DAC5-) ; sheet /IN1_N
D5_P: U35.12(DAC5+) ; sheet /IN1_P
D6_N: U35.36(DAC6-) ; sheet /IN2_N
D6_P: U35.37(DAC6+) ; sheet /IN2_P
D7_N: U35.14(DAC7-) ; sheet /IN2_N
D7_P: U35.15(DAC7+) ; sheet /IN2_P
D8_N: U35.35(DAC8-) ; sheet /IN1_N
D8_P: U35.34(DAC8+) ; sheet /IN1_P
DCLK_N: R319.1 U89.4(B) ; port DAC.DCLK_N
DCLK_P: R319.2 U89.3(A) ; port DAC.DCLK_P
GP1: C311.1 R323.1 TP41.1 U35.40(GPIO1)
GP2: C315.1 R331.1 TP45.1 U35.28(GPIO2)
GP3: R39.1 U35.27(GPIO3) ; port DAC.GPIO4  [also labelled GPIO4]
GP4: R40.1 U35.26(GPIO4) ; port DAC.GPIO3  [also labelled GPIO3]
LRCK: U35.59(DATA1) ; port DAC.LRCK
OUT1_N: port OUT1_N, sheet /OUT1_N
OUT1_P: port OUT1_P, sheet /OUT1_P
OUT2_N: port OUT2_N, sheet /OUT1_N
OUT2_P: port OUT2_P, sheet /OUT1_P
OUT3_N: port OUT3_N, sheet /OUT2_N
OUT3_P: port OUT3_P, sheet /OUT2_P
OUT4_N: port OUT4_N, sheet /OUT2_N
OUT4_P: port OUT4_P, sheet /OUT2_P
OUT5_N: port OUT5_N, sheet /OUT1_N
OUT5_P: port OUT5_P, sheet /OUT1_P
OUT6_N: port OUT6_N, sheet /OUT1_N
OUT6_P: port OUT6_P, sheet /OUT1_P
OUT7_N: port OUT7_N, sheet /OUT2_N
OUT7_P: port OUT7_P, sheet /OUT2_P
OUT8_N: port OUT8_N, sheet /OUT2_N
OUT8_P: port OUT8_P, sheet /OUT2_P
RST: R55.2 R56.1 U35.8(~{RESET}) ; port DAC.RST
SCL: R41.1 U35.22(SCL) ; port DAC.SCL
SDA: R42.1 U35.21(SDA) ; port DAC.SDA
NetR327_2: R327.2 U35.23(XOUT)
NetU35_24: U35.24(XIN/CLKIN) U93.3(A)
NetU89_5: U89.5(R) U93.4(B)

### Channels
Analog/I1/: designators *?=*?A#2 C7=C7A C8=C8A C15=C15A C19=C19A C20=C20A C27=C27A C31=C31A C35=C35A C36=C36A C43=C43A C44=C44A C51=C51A C52=C52A C287=C287A C291=C291A C295=C295A C299=C299A C303=C303A C307=C307A C311=C311A C315=C315A LOGO?=LOGO?A#2 MP4=MP4A R39=R39A R40=R40A R41=R41A R42=R42A R55=R55A R56=R56A R63=R63A R319=R319A R323=R323A R327=R327A R331=R331A TP41=TP41A TP45=TP45A U35=U35A U89=U89A U93=U93A; ports COM1=COM1&2 OUT1_N=ANALOG1.A1_N OUT1_P=ANALOG1.A1_P OUT2_N=ANALOG1.A2_N OUT2_P=ANALOG1.A2_P OUT3_N=ANALOG1.A3_N OUT3_P=ANALOG1.A3_P OUT4_N=ANALOG1.A4_N OUT4_P=ANALOG1.A4_P OUT5_N=ANALOG1.A5_N OUT5_P=ANALOG1.A5_P OUT6_N=ANALOG1.A6_N OUT6_P=ANALOG1.A6_P OUT7_N=ANALOG1.A7_N OUT7_P=ANALOG1.A7_P OUT8_N=ANALOG1.A8_N OUT8_P=ANALOG1.A8_P
Analog/I2/: designators *?=*?B#3 C7=C7B C8=C8B C15=C15B C19=C19B C20=C20B C27=C27B C31=C31B C35=C35B C36=C36B C43=C43B C44=C44B C51=C51B C52=C52B C287=C287B C291=C291B C295=C295B C299=C299B C303=C303B C307=C307B C311=C311B C315=C315B LOGO?=LOGO?B#3 MP4=MP4B R39=R39B R40=R40B R41=R41B R42=R42B R55=R55B R56=R56B R63=R63B R319=R319B R323=R323B R327=R327B R331=R331B TP41=TP41B TP45=TP45B U35=U35B U89=U89B U93=U93B; ports COM1=COM1&2 OUT1_N=ANALOG2.A1_N OUT1_P=ANALOG2.A1_P OUT2_N=ANALOG2.A2_N OUT2_P=ANALOG2.A2_P OUT3_N=ANALOG2.A3_N OUT3_P=ANALOG2.A3_P OUT4_N=ANALOG2.A4_N OUT4_P=ANALOG2.A4_P OUT5_N=ANALOG2.A5_N OUT5_P=ANALOG2.A5_P OUT6_N=ANALOG2.A6_N OUT6_P=ANALOG2.A6_P OUT7_N=ANALOG2.A7_N OUT7_P=ANALOG2.A7_P OUT8_N=ANALOG2.A8_N OUT8_P=ANALOG2.A8_P
Analog/I3/: designators *?=*?C#3 C7=C7C C8=C8C C15=C15C C19=C19C C20=C20C C27=C27C C31=C31C C35=C35C C36=C36C C43=C43C C44=C44C C51=C51C C52=C52C C287=C287C C291=C291C C295=C295C C299=C299C C303=C303C C307=C307C C311=C311C C315=C315C LOGO?=LOGO?C#3 MP4=MP4C R39=R39C R40=R40C R41=R41C R42=R42C R55=R55C R56=R56C R63=R63C R319=R319C R323=R323C R327=R327C R331=R331C TP41=TP41C TP45=TP45C U35=U35C U89=U89C U93=U93C; ports COM1=COM3&4 OUT1_N=ANALOG3.A1_N OUT1_P=ANALOG3.A1_P OUT2_N=ANALOG3.A2_N OUT2_P=ANALOG3.A2_P OUT3_N=ANALOG3.A3_N OUT3_P=ANALOG3.A3_P OUT4_N=ANALOG3.A4_N OUT4_P=ANALOG3.A4_P OUT5_N=ANALOG3.A5_N OUT5_P=ANALOG3.A5_P OUT6_N=ANALOG3.A6_N OUT6_P=ANALOG3.A6_P OUT7_N=ANALOG3.A7_N OUT7_P=ANALOG3.A7_P OUT8_N=ANALOG3.A8_N OUT8_P=ANALOG3.A8_P
Analog/I4/: designators *?=*?D#3 C7=C7D C8=C8D C15=C15D C19=C19D C20=C20D C27=C27D C31=C31D C35=C35D C36=C36D C43=C43D C44=C44D C51=C51D C52=C52D C287=C287D C291=C291D C295=C295D C299=C299D C303=C303D C307=C307D C311=C311D C315=C315D LOGO?=LOGO?D#3 MP4=MP4D R39=R39D R40=R40D R41=R41D R42=R42D R55=R55D R56=R56D R63=R63D R319=R319D R323=R323D R327=R327D R331=R331D TP41=TP41D TP45=TP45D U35=U35D U89=U89D U93=U93D; ports COM1=COM3&4 OUT1_N=ANALOG4.A1_N OUT1_P=ANALOG4.A1_P OUT2_N=ANALOG4.A2_N OUT2_P=ANALOG4.A2_P OUT3_N=ANALOG4.A3_N OUT3_P=ANALOG4.A3_P OUT4_N=ANALOG4.A4_N OUT4_P=ANALOG4.A4_P OUT5_N=ANALOG4.A5_N OUT5_P=ANALOG4.A5_P OUT6_N=ANALOG4.A6_N OUT6_P=ANALOG4.A6_P OUT7_N=ANALOG4.A7_N OUT7_P=ANALOG4.A7_P OUT8_N=ANALOG4.A8_N OUT8_P=ANALOG4.A8_P

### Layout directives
differential pair: D1_N_, D1_P_, D2_N_, D2_P_, D3_N_, D3_P_, D4_N_, D4_P_, D5_N_, D5_P_, D6_N_, D6_P_, D7_N_, D7_P_, D8_N_, D8_P_

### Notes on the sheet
- Main Clock
- DAC Inputs
- DAC Outputs
- Core Power
- Parts Checked for =Value and Consistency
- Voltage Legend:
  SW+2V = 2V from switcher
  SW+4V = 4V from switcher
  +/- 7V step down from +/- 10V switcher
  DAC Power
  AVCC_3.3V = Power Reference for DAC
  VCCA_3.3V = Digital Power for DAC
  DVDD_1.2V Core = Digital Core for DAC
  Phase Power:
  +7V Power from front end power.
  VREF-PH = 3.0V Reference for Phase Detector
  FPGA Power:
  AVCC1V8 = XADCVCC
  VCC3V3 = VCC
  VCC2V5 = FPGA 2.5V dpwr LVDS Power
  VCC1V8 = VDD = VCCAUX
  VCC1V0 = VCCINT = VCCBRAM
  VREG = 5.1V Linear from FPGA Power
  PCIe
  AVTT = 1.2V
  AVCC = 1.0V
- Clock lines and reset could be shared in principle.
  You also routed more lines than we really need.
  1 fast clock (LVDS, SN65LVDS104 for FO)
  1 BCLK
  1 LRCLK
  4 D lines
  2 I2C lines
  is needed per DAC.
  There will be a difference between Artix-7 and Artix Ultrascale with later only supporting 1.8V.
  Daniel

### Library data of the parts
C7 C8 C43 C44 C291 C303 = ChipCap: C1210 10uF; Part Number: CL32B106KBJNNNE
C15 C19 C20 C27 C31 C35 C36 C51 C52 C287 C295 C299 C307 = ChipCap: C0201 0.1uF; Part Number: 490-GRM033Z71C104KE14DCT-ND
C311 C315 = ChipCap: C0402 0.2n; Part Number: 0402N201J500CT
LOGO? = LIGO_logo
MP4 = CMP-33535-000022-1: HEATSINK FOR TO-268
R39 R40 = ChipRes1: R0201 47k; Part Number: RMCF0201FT47K0CT-ND
R41 R42 = ChipRes1: R0201 2k; Part Number: ERA-1AEB202C
R55 R63 = ChipRes1: R0201 100k; Part Number: ERJ-1GNF1003C
R56 = ChipRes1: NL
R319 = ChipRes1: R0402 100; Part Number: RR0510P-101-D
R323 R331 = ChipRes1: R0402 100k; Part Number: ERA-2AEB104X
R327 = ChipRes1
TP41 TP45 = TP_SMD: Testpoint,SMD, micro miniature; Part Number: 36-5017CT-ND
U35 = ESS9038PRO: Flagship 32-Bit HyperStream II 8-Channel Audio DAC; Part Number: ES9038PRO
U89 = SN65LVDT2DBV: Single LVDS Receiver with 100 Ohm termination; Part Number: SN65LVDT2DBVR
U93 = SN74LVC1T45: Single-Bit Dual Supply Transceiver; Part Number: SN74AVC1T45DBVT

## Sheet LD32_FrontEnd.SchDoc: Front End
size B; SheetNumber: 15; SheetTotal: 17
Used 16 times, as channels Analog/I1//, Analog/I1//, Analog/I1//, Analog/I1//, Analog/I2//, Analog/I2//, Analog/I2//, Analog/I2//, Analog/I3//, Analog/I3//, Analog/I3//, Analog/I3//, Analog/I4//, Analog/I4//, Analog/I4//, Analog/I4//. Parts and nets are listed once, with the designators drawn on the sheet.
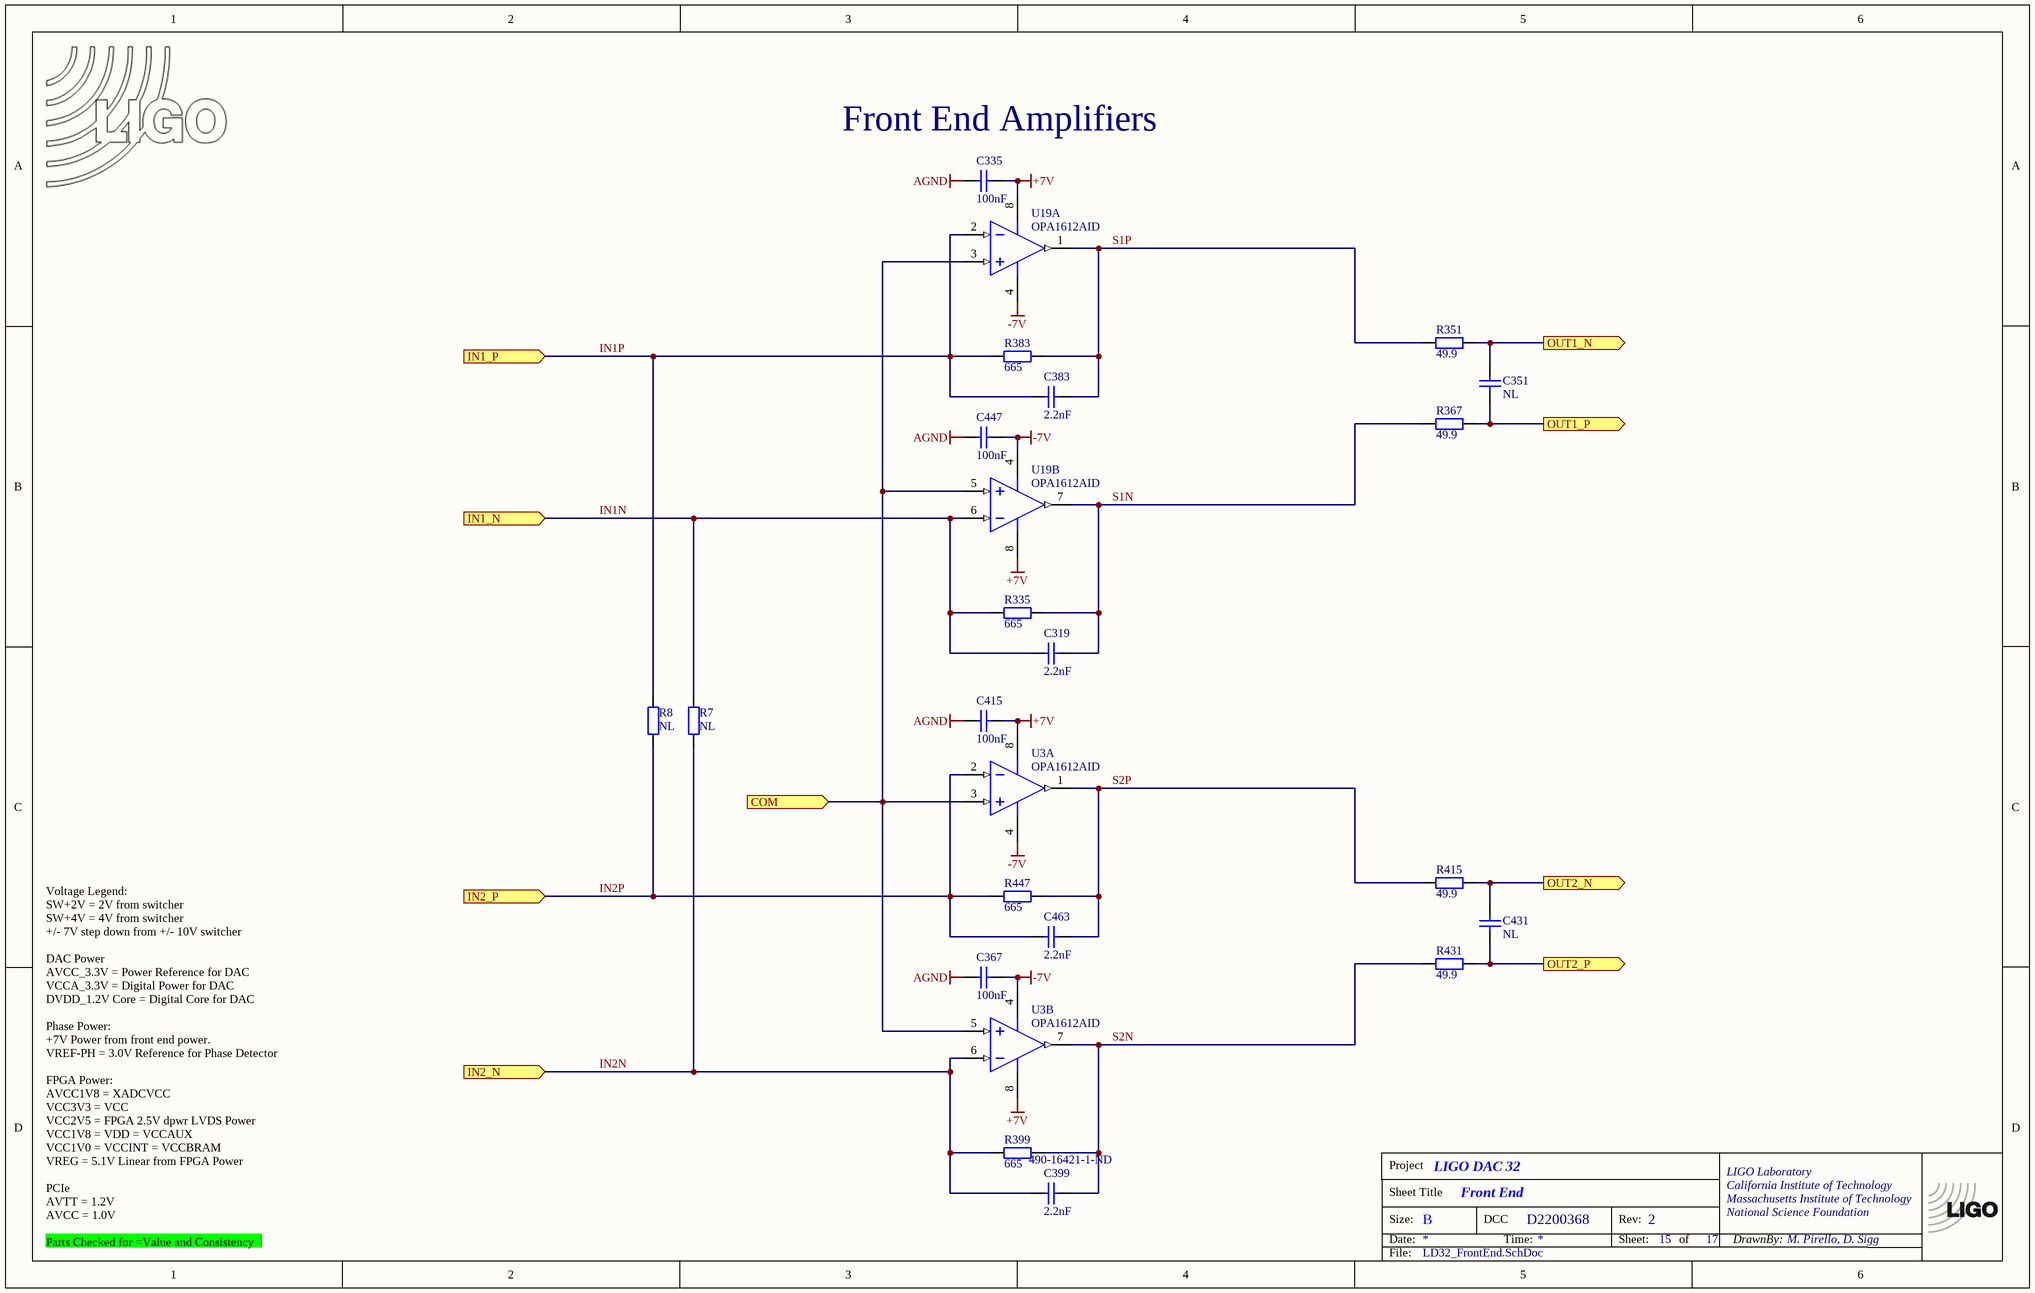
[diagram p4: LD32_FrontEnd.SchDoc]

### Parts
*?  TitleBlock  (value not drawn)  (graphical)
C319  2.2nF  [CC1608-0603]
C335  100nF  [CC1005-0402]
C351  NL  [CC1005-0402]
C367  100nF  [CC1005-0402]
C383  2.2nF  [CC1608-0603]
C399  Supplier Part Number 1: 490-16421-1-ND  [CC1608-0603]  (hidden comment: 2.2nF)
C415  100nF  [CC1005-0402]
C431  NL  [CC1005-0402]
C447  100nF  [CC1005-0402]
C463  2.2nF  [CC1608-0603]
LOGO?  LIGO logo  [LIGO_LOGO]  (value not drawn)  (graphical)
R7  NL  [CR1005-0402]
R8  NL  [CR1005-0402]
R335  665  [CR1608-0603]
R351  49.9  [CR1005-0402]
R367  49.9  [CR1005-0402]
R383  665  [CR1608-0603]
R399  665  [CR1608-0603]
R415  49.9  [CR1005-0402]
R431  49.9  [CR1005-0402]
R447  665  [CR1608-0603]
U3  OPA1612AID  [D0008A_M]  (parts A,B of 2)
U19  OPA1612AID  [D0008A_M]  (parts A,B of 2)

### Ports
COM (in), IN1_N (in), IN1_P (in), IN2_N (in), IN2_P (in), OUT1_N (out), OUT1_P (out), OUT2_N (out), OUT2_P (out)

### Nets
+7V: C335.1 C415.1 U3.8(V+) U19.8(V+)
-7V: C367.1 C447.1 U3.4(V-) U19.4(V-)
AGND: C335.2 C367.2 C415.2 C447.2
COM: U3.3(IN_A+) U3.5(IN_B+) U19.3(IN_A+) U19.5(IN_B+) ; port COM
IN1N: C319.2 R7.2 R335.1 U19.6(IN_B-) ; port IN1_N
IN1P: C383.2 R8.2 R383.1 U19.2(IN_A-) ; port IN1_P
IN2N: C399.2 R7.1 R399.1 U3.6(IN_B-) ; port IN2_N
IN2P: C463.2 R8.1 R447.1 U3.2(IN_A-) ; port IN2_P
OUT1_N: C351.1 R351.2 ; port OUT1_N
OUT1_P: C351.2 R367.2 ; port OUT1_P
OUT2_N: C431.1 R415.2 ; port OUT2_N
OUT2_P: C431.2 R431.2 ; port OUT2_P
S1N: C319.1 R335.2 R367.1 U19.7(OUT_B)
S1P: C383.1 R351.1 R383.2 U19.1(OUT_A)
S2N: C399.1 R399.2 R431.1 U3.7(OUT_B)
S2P: C463.1 R415.1 R447.2 U3.1(OUT_A)

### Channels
Analog/I1//: designators *?=*?A#3 C319=C319A C335=C335A C351=C351A C367=C367A C383=C383A C399=C399A C415=C415A C431=C431A C447=C447A C463=C463A LOGO?=LOGO?A#3 R7=R7A R8=R8A R335=R335A R351=R351A R367=R367A R383=R383A R399=R399A R415=R415A R431=R431A R447=R447A U3=U3A U19=U19A; ports COM=COM1&2 IN1_N=D4_N_ IN1_P=D4_P_ IN2_N=D2_N_ IN2_P=D2_P_ OUT1_N=ANALOG1.A2_N OUT1_P=ANALOG1.A2_P OUT2_N=ANALOG1.A4_N OUT2_P=ANALOG1.A4_P
Analog/I1//: designators *?=*?B#1 C319=C319B C335=C335B C351=C351B C367=C367B C383=C383B C399=C399B C415=C415B C431=C431B C447=C447B C463=C463B LOGO?=LOGO?B#1 R7=R7B R8=R8B R335=R335B R351=R351B R367=R367B R383=R383B R399=R399B R415=R415B R431=R431B R447=R447B U3=U3B U19=U19B; ports COM=COM1&2 IN1_N=D1_N_ IN1_P=D1_P_ IN2_N=D3_N_ IN2_P=D3_P_ OUT1_N=ANALOG1.A1_N OUT1_P=ANALOG1.A1_P OUT2_N=ANALOG1.A3_N OUT2_P=ANALOG1.A3_P
Analog/I1//: designators *?=*?C#1 C319=C319C C335=C335C C351=C351C C367=C367C C383=C383C C399=C399C C415=C415C C431=C431C C447=C447C C463=C463C LOGO?=LOGO?C#1 R7=R7C R8=R8C R335=R335C R351=R351C R367=R367C R383=R383C R399=R399C R415=R415C R431=R431C R447=R447C U3=U3C U19=U19C; ports COM=COM1&2 IN1_N=D5_N_ IN1_P=D5_P_ IN2_N=D7_N_ IN2_P=D7_P_ OUT1_N=ANALOG1.A5_N OUT1_P=ANALOG1.A5_P OUT2_N=ANALOG1.A7_N OUT2_P=ANALOG1.A7_P
Analog/I1//: designators *?=*?D#1 C319=C319D C335=C335D C351=C351D C367=C367D C383=C383D C399=C399D C415=C415D C431=C431D C447=C447D C463=C463D LOGO?=LOGO?D#1 R7=R7D R8=R8D R335=R335D R351=R351D R367=R367D R383=R383D R399=R399D R415=R415D R431=R431D R447=R447D U3=U3D U19=U19D; ports COM=COM1&2 IN1_N=D8_N_ IN1_P=D8_P_ IN2_N=D6_N_ IN2_P=D6_P_ OUT1_N=ANALOG1.A6_N OUT1_P=ANALOG1.A6_P OUT2_N=ANALOG1.A8_N OUT2_P=ANALOG1.A8_P
Analog/I2//: designators end in E; ports COM=COM1&2 IN1_N=D4_N_ IN1_P=D4_P_ IN2_N=D2_N_ IN2_P=D2_P_ OUT1_N=ANALOG2.A2_N OUT1_P=ANALOG2.A2_P OUT2_N=ANALOG2.A4_N OUT2_P=ANALOG2.A4_P
Analog/I2//: designators end in F; ports COM=COM1&2 IN1_N=D1_N_ IN1_P=D1_P_ IN2_N=D3_N_ IN2_P=D3_P_ OUT1_N=ANALOG2.A1_N OUT1_P=ANALOG2.A1_P OUT2_N=ANALOG2.A3_N OUT2_P=ANALOG2.A3_P
Analog/I2//: designators end in G; ports COM=COM1&2 IN1_N=D5_N_ IN1_P=D5_P_ IN2_N=D7_N_ IN2_P=D7_P_ OUT1_N=ANALOG2.A5_N OUT1_P=ANALOG2.A5_P OUT2_N=ANALOG2.A7_N OUT2_P=ANALOG2.A7_P
Analog/I2//: designators end in H; ports COM=COM1&2 IN1_N=D8_N_ IN1_P=D8_P_ IN2_N=D6_N_ IN2_P=D6_P_ OUT1_N=ANALOG2.A6_N OUT1_P=ANALOG2.A6_P OUT2_N=ANALOG2.A8_N OUT2_P=ANALOG2.A8_P
Analog/I3//: designators end in I; ports COM=COM3&4 IN1_N=D4_N_ IN1_P=D4_P_ IN2_N=D2_N_ IN2_P=D2_P_ OUT1_N=ANALOG3.A2_N OUT1_P=ANALOG3.A2_P OUT2_N=ANALOG3.A4_N OUT2_P=ANALOG3.A4_P
Analog/I3//: designators end in J; ports COM=COM3&4 IN1_N=D1_N_ IN1_P=D1_P_ IN2_N=D3_N_ IN2_P=D3_P_ OUT1_N=ANALOG3.A1_N OUT1_P=ANALOG3.A1_P OUT2_N=ANALOG3.A3_N OUT2_P=ANALOG3.A3_P
Analog/I3//: designators end in K; ports COM=COM3&4 IN1_N=D5_N_ IN1_P=D5_P_ IN2_N=D7_N_ IN2_P=D7_P_ OUT1_N=ANALOG3.A5_N OUT1_P=ANALOG3.A5_P OUT2_N=ANALOG3.A7_N OUT2_P=ANALOG3.A7_P
Analog/I3//: designators end in L; ports COM=COM3&4 IN1_N=D8_N_ IN1_P=D8_P_ IN2_N=D6_N_ IN2_P=D6_P_ OUT1_N=ANALOG3.A6_N OUT1_P=ANALOG3.A6_P OUT2_N=ANALOG3.A8_N OUT2_P=ANALOG3.A8_P
Analog/I4//: designators end in M; ports COM=COM3&4 IN1_N=D4_N_ IN1_P=D4_P_ IN2_N=D2_N_ IN2_P=D2_P_ OUT1_N=ANALOG4.A2_N OUT1_P=ANALOG4.A2_P OUT2_N=ANALOG4.A4_N OUT2_P=ANALOG4.A4_P
Analog/I4//: designators end in N; ports COM=COM3&4 IN1_N=D1_N_ IN1_P=D1_P_ IN2_N=D3_N_ IN2_P=D3_P_ OUT1_N=ANALOG4.A1_N OUT1_P=ANALOG4.A1_P OUT2_N=ANALOG4.A3_N OUT2_P=ANALOG4.A3_P
Analog/I4//: designators end in O; ports COM=COM3&4 IN1_N=D5_N_ IN1_P=D5_P_ IN2_N=D7_N_ IN2_P=D7_P_ OUT1_N=ANALOG4.A5_N OUT1_P=ANALOG4.A5_P OUT2_N=ANALOG4.A7_N OUT2_P=ANALOG4.A7_P
Analog/I4//: designators end in P; ports COM=COM3&4 IN1_N=D8_N_ IN1_P=D8_P_ IN2_N=D6_N_ IN2_P=D6_P_ OUT1_N=ANALOG4.A6_N OUT1_P=ANALOG4.A6_P OUT2_N=ANALOG4.A8_N OUT2_P=ANALOG4.A8_P

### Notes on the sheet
- (near C335) Front End Amplifiers
- Parts Checked for =Value and Consistency
- Voltage Legend:
  SW+2V = 2V from switcher
  SW+4V = 4V from switcher
  +/- 7V step down from +/- 10V switcher
  DAC Power
  AVCC_3.3V = Power Reference for DAC
  VCCA_3.3V = Digital Power for DAC
  DVDD_1.2V Core = Digital Core for DAC
  Phase Power:
  +7V Power from front end power.
  VREF-PH = 3.0V Reference for Phase Detector
  FPGA Power:
  AVCC1V8 = XADCVCC
  VCC3V3 = VCC
  VCC2V5 = FPGA 2.5V dpwr LVDS Power
  VCC1V8 = VDD = VCCAUX
  VCC1V0 = VCCINT = VCCBRAM
  VREG = 5.1V Linear from FPGA Power
  PCIe
  AVTT = 1.2V
  AVCC = 1.0V

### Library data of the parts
C319 C383 C399 C463 = ChipCap: C0603 2.2n; Part Number: GCM1885C1H222FA16D
C335 C367 C415 C447 = ChipCap: as C59 on sheet LD32_TOP
C351 C431 = ChipCap
LOGO? = LIGO_logo
R7 R8 = ChipRes1
R335 R383 R399 R447 = ChipRes1: R0603 665; Part Number: RQ73C1J665RBTD
R351 R367 R415 R431 = ChipRes1: R0402 49.9; Part Number: ERA-2AEB49R9X
U3 U19 = CMP-0808-00013-2: 1.1 nV/rtHz Noise, Low Power, Precision Operational Amplifier, 4.5 to 36 V, -40 to 85 degC, 8-pin SOIC (D8), Green (RoHS & no Sb/Br)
